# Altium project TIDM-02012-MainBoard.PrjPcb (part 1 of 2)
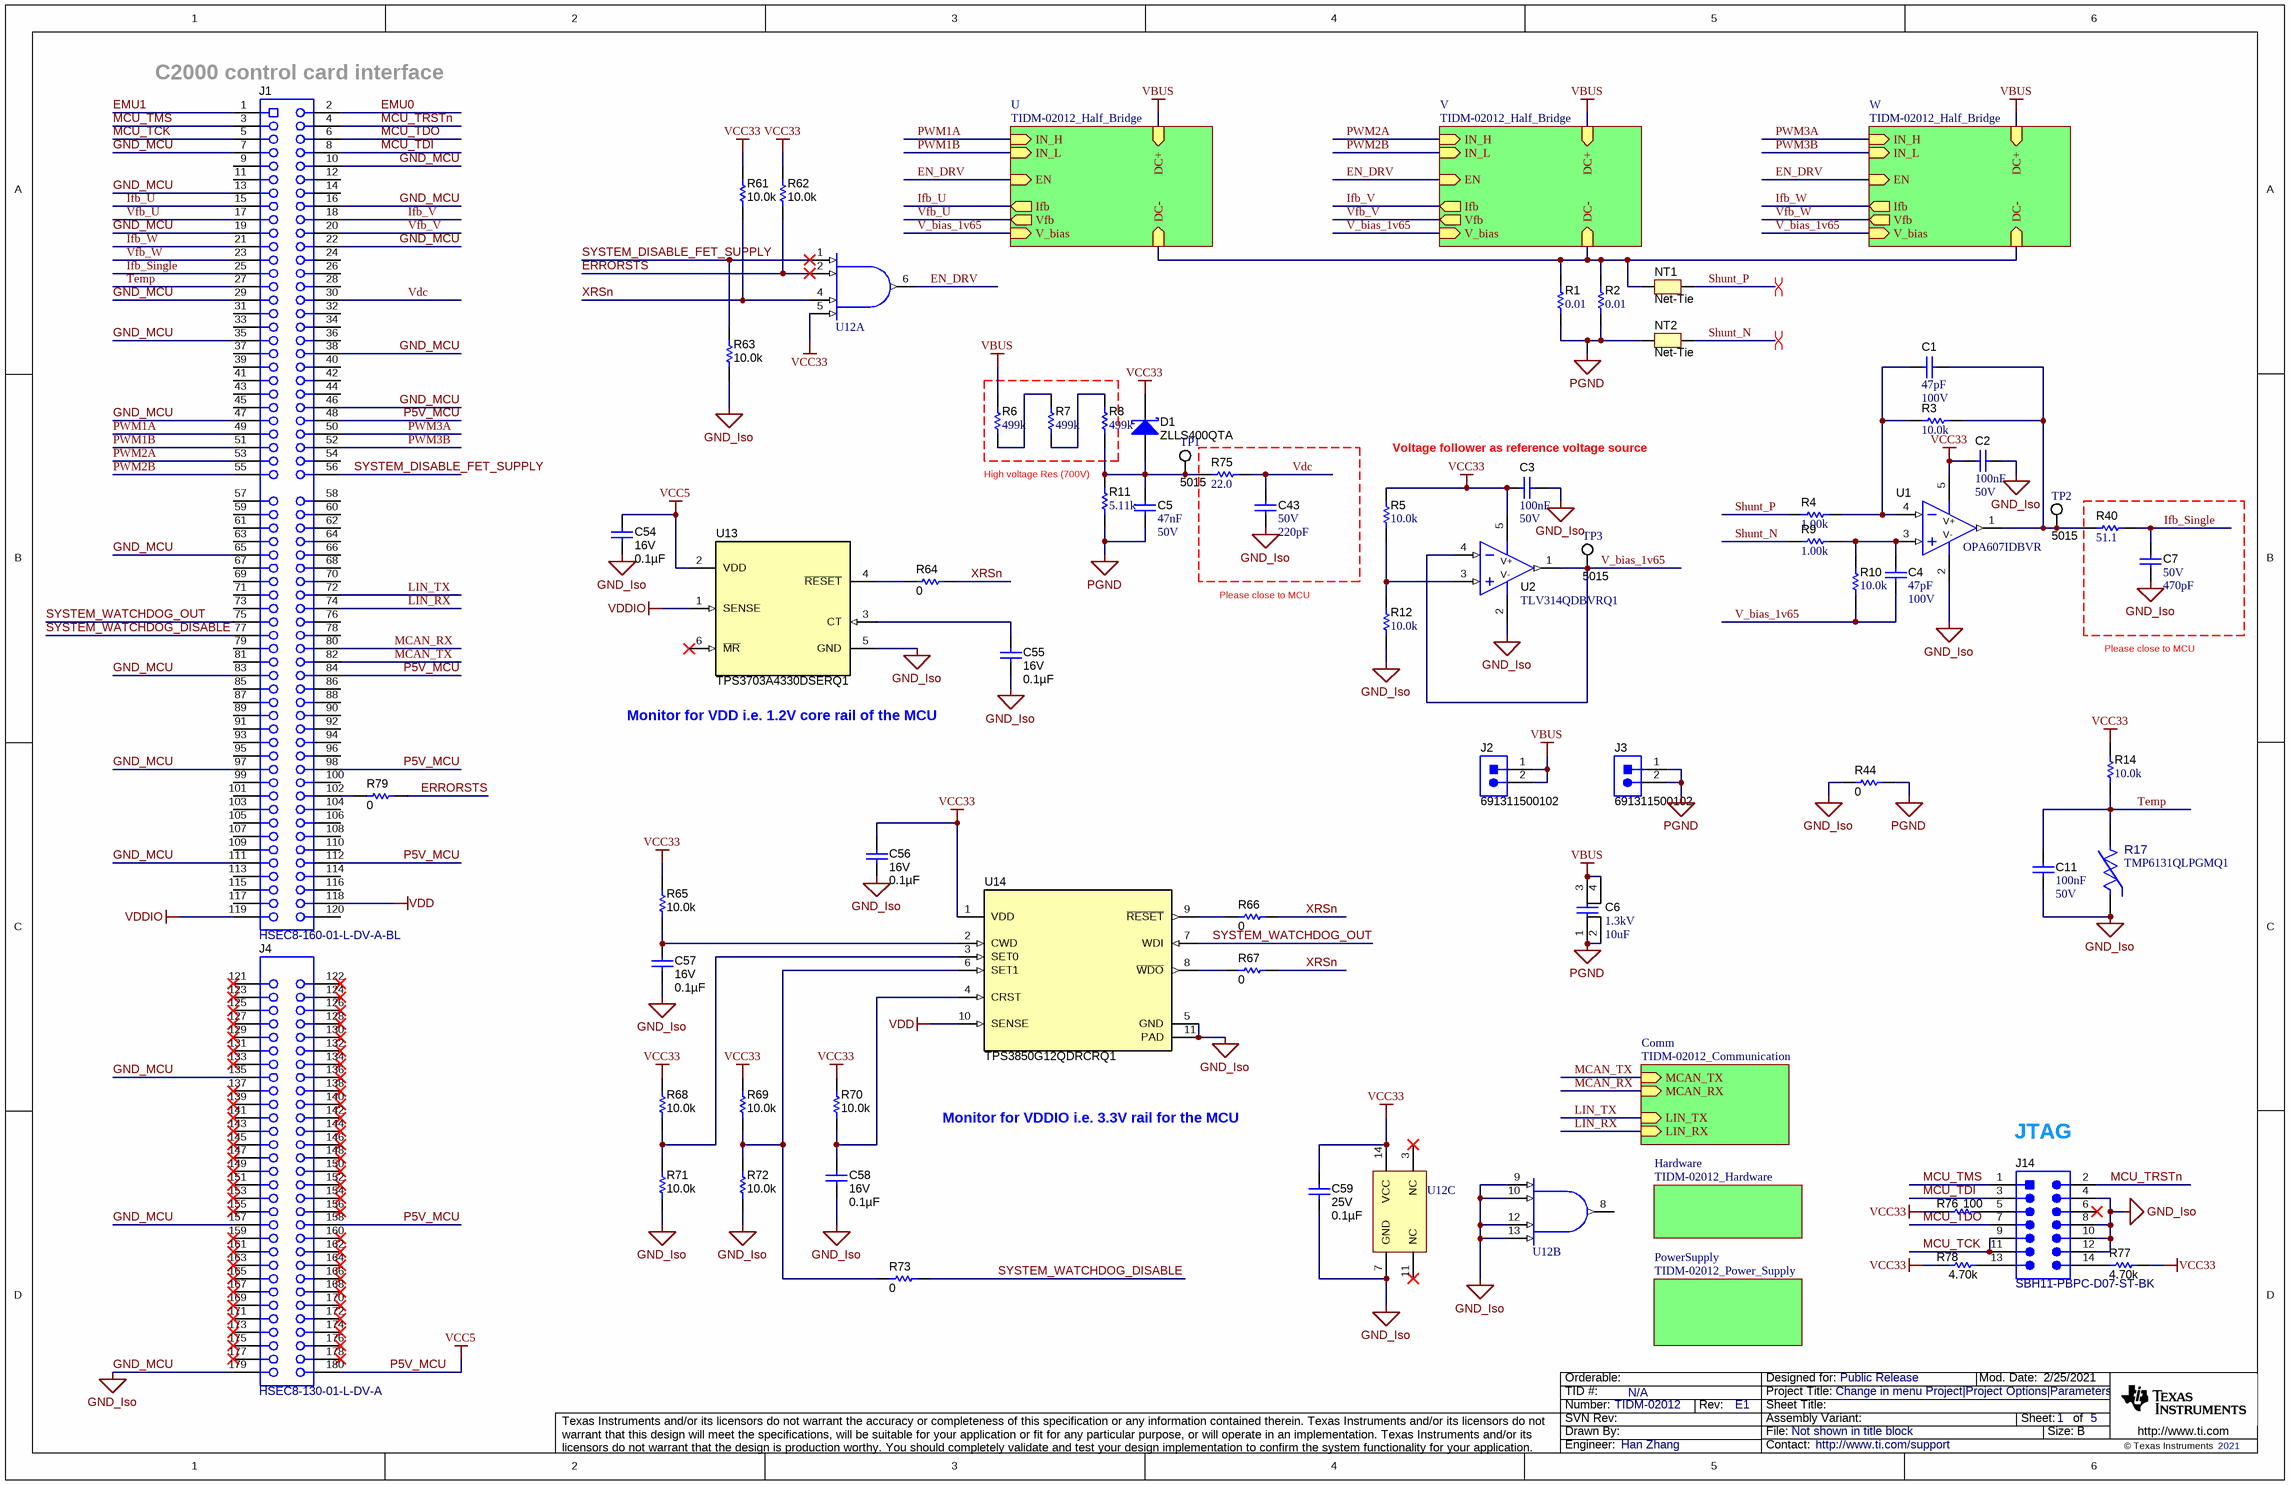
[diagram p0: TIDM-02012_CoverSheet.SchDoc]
CopyrightYear: 2021; PCB_Layout: Han Zhang; PCB_Rev: E1; PRJ_Customer: Public Release; PRJ_Engineer: Han Zhang; PRJ_Number: TIDM-02012; PRJ_Title: Change in menu Project|Project Options|Parameters; SCH_Rev: E1; TechSupport: http://www.ti.com/support; TID: N/A
5 sheets, 301 parts. Net scope: hierarchical (ports join the sheet entries above them; power ports are global).
Board file: TIDM-02012_MainBoard.PcbDoc
Sheets:
  TIDM-02012_CoverSheet.SchDoc
    PowerSupply = TIDM-02012_Power_Supply.SchDoc
    U = TIDM-02012_Half_Bridge.SchDoc
    Hardware = TIDM-02012_Hardware.SchDoc
    W = TIDM-02012_Half_Bridge.SchDoc
    V = TIDM-02012_Half_Bridge.SchDoc
    Comm = TIDM-02012_Communication.SchDoc

## Sheet TIDM-02012_CoverSheet.SchDoc
size 431 x 279 mm; Date: Not shown in title block; ApprovedBy: Not shown in title block; CheckedBy: Not shown in title block; Author: Not shown in title block; CompanyName: Not shown in title block; Engineer: Not shown in title block; Organization: Not shown in title block; Address1: Not shown in title block; Address2: Not shown in title block; Address3: Not shown in title block; Address4: Not shown in title block; DocumentNumber: 2; Revision: Use project parameter SCH_Rev; SheetNumber: 1; SheetTotal: 5; PageSetup: Record=PageOptions¦CenterHorizontal=True¦CenterVertical=True¦PrintScale=1.00¦XCorrection=1.00¦YCorrection=1.00¦PrintKind=0¦BorderSize=5000000¦LeftOffset=0¦BottomOffset=0¦Orientation=2¦PaperLength=1000¦PaperWidth=1000¦Scale=100¦PaperSource=15¦PrintQuality=600¦MediaType=1¦DitherType=10¦PaperKind=Letter¦PrintScaleMode=1

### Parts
C1  ValueDisplayed: 47pF  VDC_V: 100V  [0603]  (hidden comment: C0603C470J1GACAUTO)
C2  Cap_F: 100nF  VDC_V: 50V  [0603]  (hidden comment: C0603C104K5RACTU)
C3  Cap_F: 100nF  VDC_V: 50V  [0603]  (hidden comment: C0603C104K5RACTU)
C4  ValueDisplayed: 47pF  VDC_V: 100V  [0603]  (hidden comment: C0603C470J1GACAUTO)
C5  Cap_F: 47nF  VDC_V: 50V  [0603]  (hidden comment: 06035C473JAT2A)
C6  VDC_V: 1.3kV  ValueDisplayed: 10uF  [B32776_4200x2800x3700]  (hidden comment: B32776G1106K)
C7  VDC_V: 50V  ValueDisplayed: 470pF  [0603]  (hidden comment: GRM1885C1H471JA01D)
C11  Cap_F: 100nF  VDC_V: 50V  [0603]  (hidden comment: C0603C104K5RACTU)
C43  VDC_V: 50V  ValueDisplayed: 220pF  [0603]  (hidden comment: GRM1885C1H221JA01D)
C54  VDC_V: 16V  ValueDisplayed: 0.1µF  [0402]  (hidden comment: GCM155R71C104JA55D)
C55  VDC_V: 16V  ValueDisplayed: 0.1µF  [0402]  (hidden comment: GCM155R71C104JA55D)
C56  VDC_V: 16V  ValueDisplayed: 0.1µF  [0402]  (hidden comment: GCM155R71C104JA55D)
C57  VDC_V: 16V  ValueDisplayed: 0.1µF  [0402]  (hidden comment: GCM155R71C104JA55D)
C58  VDC_V: 16V  ValueDisplayed: 0.1µF  [0402]  (hidden comment: GCM155R71C104JA55D)
C59  VDC_V: 25V  ValueDisplayed: 0.1µF  [0402]  (hidden comment: CGA2B3X7R1E104K050BB)
D1  ZLLS400QTA  [SOD-323]
J1  HSEC8-160-01-L-DV-A-BL  [controlCARD-120HSEC]
J2  691311500102  [Wurth_691311500102]
J3  691311500102  [Wurth_691311500102]
J4  HSEC8-130-01-L-DV-A  [controlCARD-180HSEC-60pinAddon]
J14  SBH11-PBPC-D07-ST-BK  [CONN_SBH11-PBPC-D07-ST-BK]
NT1  Net-Tie  [Net-Tie_10milWide_30milLong]  (net tie, no BOM)
NT2  Net-Tie  [Net-Tie_10milWide_30milLong]  (net tie, no BOM)
R1  ValueDisplayed: 0.01  [1206]  (hidden comment: WSLP1206R0100FEA)
R2  ValueDisplayed: 0.01  [1206]  (hidden comment: WSLP1206R0100FEA)
R3  ValueDisplayed: 10.0k  [0603]  (hidden comment: RC0603FR-0710KL)
R4  ValueDisplayed: 1.00k  [0603]  (hidden comment: RC0603FR-071KL)
R5  ValueDisplayed: 10.0k  [0603]  (hidden comment: RC0603FR-0710KL)
R6  ValueDisplayed: 499k  [1206]  (hidden comment: ERJ-8ENF4993V)
R7  ValueDisplayed: 499k  [1206]  (hidden comment: ERJ-8ENF4993V)
R8  ValueDisplayed: 499k  [1206]  (hidden comment: ERJ-8ENF4993V)
R9  ValueDisplayed: 1.00k  [0603]  (hidden comment: RC0603FR-071KL)
R10  ValueDisplayed: 10.0k  [0603]  (hidden comment: RC0603FR-0710KL)
R11  ValueDisplayed: 5.11k  [1206]  (hidden comment: ERJ-8ENF5111V)
R12  ValueDisplayed: 10.0k  [0603]  (hidden comment: RC0603FR-0710KL)
R14  ValueDisplayed: 10.0k  [0603]  (hidden comment: RC0603FR-0710KL)
R17  TMP6131QLPGMQ1  [LPG0002A-MFG]
R40  ValueDisplayed: 51.1  [0603]  (hidden comment: RC0603FR-0751R1L)
R44  ValueDisplayed: 0  [0402]  (hidden comment: ERJ-2GE0R00X)
R61  ValueDisplayed: 10.0k  [0402]  (hidden comment: ERJPA2F1002X)
R62  ValueDisplayed: 10.0k  [0402]  (hidden comment: ERJPA2F1002X)
R63  ValueDisplayed: 10.0k  [0402]  (hidden comment: ERJPA2F1002X)
R64  ValueDisplayed: 0  [0402]  (hidden comment: ERJ-2GE0R00X)
R65  ValueDisplayed: 10.0k  [0402]  (hidden comment: ERJPA2F1002X)
R66  ValueDisplayed: 0  [0402]  (hidden comment: ERJ-2GE0R00X)
R67  ValueDisplayed: 0  [0402]  (hidden comment: ERJ-2GE0R00X)
R68  ValueDisplayed: 10.0k  [0402]  (hidden comment: ERJPA2F1002X)
R69  ValueDisplayed: 10.0k  [0402]  (hidden comment: ERJPA2F1002X)
R70  ValueDisplayed: 10.0k  [0402]  (hidden comment: ERJPA2F1002X)
R71  ValueDisplayed: 10.0k  [0402]  (hidden comment: ERJPA2F1002X)
R72  ValueDisplayed: 10.0k  [0402]  (hidden comment: ERJPA2F1002X)
R73  ValueDisplayed: 0  [0402]  (hidden comment: ERJ-2GE0R00X)
R75  ValueDisplayed: 22.0  [0603]  (hidden comment: RC0603FR-0722RL)
R76  ValueDisplayed: 100  [0603]  (hidden comment: ERJ-3EKF1000V)
R77  ValueDisplayed: 4.70k  [0603]  (hidden comment: RC0603FR-074K7L)
R78  ValueDisplayed: 4.70k  [0603]  (hidden comment: RC0603FR-074K7L)
R79  ValueDisplayed: 0  [0402]  (hidden comment: ERJ-2GE0R00X)
TP1  5015  [Testpoint_Keystone_Miniature]
TP2  5015  [Testpoint_Keystone_Miniature]
TP3  5015  [Testpoint_Keystone_Miniature]
U1  OPA607IDBVR  [DBV0005A_N]
U2  TLV314QDBVRQ1  [DBV0005A_N]
U12  SN74HC21QPWRG4Q1  [PW0014A_N]  (value not drawn)  (parts A,B,C of 3)
U13  TPS3703A4330DSERQ1  [DSE0006A]
U14  TPS3850G12QDRCRQ1  [DRC0010R]

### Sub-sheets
Comm = TIDM-02012_Communication: LIN_RX (in), MCAN_TX (in), MCAN_RX (in), LIN_TX (in)
Hardware = TIDM-02012_Hardware: no entries
PowerSupply = TIDM-02012_Power_Supply: no entries
U = TIDM-02012_Half_Bridge: DC+ (in), IN_H (in), IN_L (in), DC- (in), V_bias (in), Ifb (out), EN (in), Vfb (out)
V = TIDM-02012_Half_Bridge: DC+ (in), IN_H (in), IN_L (in), DC- (in), V_bias (in), Ifb (out), EN (in), Vfb (out)
W = TIDM-02012_Half_Bridge: DC+ (in), IN_H (in), IN_L (in), DC- (in), V_bias (in), Ifb (out), EN (in), Vfb (out)

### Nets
GND_MCU: C2.1 C3.1 C7.2 C11.1 C43.2 C54.2 C55.2 C56.2 C57.2 C58.2 C59.2 J1.7 J1.10 J1.13 J1.16 J1.19 J1.22 J1.29 J1.35 J1.38 J1.46 J1.47 J1.65 J1.83 J1.97 J1.111 J4.135 J4.157 J4.179 J14.4 J14.8 J14.10 J14.12 R12.1 R17.1(-) R44.1 R63.1 R71.1 R72.1 U1.2(V-) U2.2(V-) U12.7(GND) U12.9(2A) U12.10(2B) U12.12(2C) U12.13(2D) U13.5(GND) U14.5(GND) U14.11(PAD)  [also labelled GND_Iso]
P5V_MCU: C54.1 J1.48 J1.84 J1.98 J1.112 J4.158 J4.180 U13.2(VDD)  [also labelled VCC5]
PGND: C5.2 C6.1 C6.2 J3.1 J3.2 NT2.1 R1.1 R2.1 R11.1 R44.2
VBUS: C6.3 C6.4 J2.1 J2.2 R6.2 ; sheet U/DC+, sheet W/DC+, sheet V/DC+
VCC33: C2.2 C3.2 C56.1 C59.1 D1.1(K) R5.2 R14.2 R61.2 R62.2 R65.2 R68.2 R69.2 R70.2 R76.1 R77.2 R78.1 U1.5(V+) U2.5(V+) U12.5(1D) U12.14(VCC) U14.1(VDD)
VDD: J1.118 U14.10(SENSE)
VDDIO: J1.119 U13.1(SENSE)
DC-: NT1.1 R1.2 R2.2 ; sheet U/DC-, sheet W/DC-, sheet V/DC-
EMU0: J1.2
EMU1: J1.1
EN_DRV: U12.6(1Y) ; sheet U/EN, sheet W/EN, sheet V/EN
ERRORSTS: R62.1 R79.2 U12.2(1B)
Ifb_Single: C7.1 J1.25 R40.2
Ifb_U: J1.15 ; sheet U/Ifb
Ifb_V: J1.18 ; sheet V/Ifb
Ifb_W: J1.21 ; sheet W/Ifb
LIN_RX: J1.74 ; sheet Comm/LIN_RX
LIN_TX: J1.72 ; sheet Comm/LIN_TX
MCAN_RX: J1.80 ; sheet Comm/MCAN_RX
MCAN_TX: J1.82 ; sheet Comm/MCAN_TX
MCU_TCK: J1.5 J14.9 J14.11
MCU_TDI: J1.8 J14.3
MCU_TDO: J1.6 J14.7
MCU_TMS: J1.3 J14.1
MCU_TRSTn: J1.4 J14.2
PWM1A: J1.49 ; sheet U/IN_H
PWM1B: J1.51 ; sheet U/IN_L
PWM2A: J1.53 ; sheet V/IN_H
PWM2B: J1.55 ; sheet V/IN_L
PWM3A: J1.50 ; sheet W/IN_H
PWM3B: J1.52 ; sheet W/IN_L
Shunt_N: NT2.2 R9.1
Shunt_P: NT1.2 R4.1
SYSTEM_DISABLE_FET_SUPPLY: J1.56 R63.2 U12.1(1A)
SYSTEM_WATCHDOG_DISABLE: J1.77 R73.2
SYSTEM_WATCHDOG_OUT: J1.75 U14.7(WDI)
Temp: C11.2 J1.27 R14.1 R17.2(+)
V_bias_1v65: C4.2 R10.1 TP3.1 U2.1(OUT) U2.4(IN-) ; sheet U/V_bias, sheet W/V_bias, sheet V/V_bias
Vdc: C43.1 J1.30 R75.2
Vfb_U: J1.17 ; sheet U/Vfb
Vfb_V: J1.20 ; sheet V/Vfb
Vfb_W: J1.23 ; sheet W/Vfb
XRSn: R61.1 R64.2 R66.2 R67.2 U12.4(1C)
NetC1_1: C1.1 R3.2 R40.1 TP2.1 U1.1(OUT)
NetC1_2: C1.2 R3.1 R4.2 U1.4(IN-)
NetC4_1: C4.1 R9.2 R10.2 U1.3(IN+)
NetC5_1: C5.1 D1.2(A) R8.1 R11.2 R75.1 TP1.1
NetC55_1: C55.1 U13.3(CT)
NetC57_1: C57.1 R65.1 U14.2(CWD)
NetC58_1: C58.1 R70.1 U14.4(CRST)
NetJ1_102: J1.102 R79.1
NetJ14_5: J14.5 R76.2
NetJ14_13: J14.13 R78.2
NetJ14_14: J14.14 R77.1
NetR5_1: R5.1 R12.2 U2.3(IN+)
NetR6_1: R6.1 R7.2
NetR7_1: R7.1 R8.2
NetR64_1: R64.1 U13.4(~{RESET})
NetR66_1: R66.1 U14.9(~{RESET})
NetR67_1: R67.1 U14.8(~{WDO})
NetR68_1: R68.1 R71.2 U14.3(SET0)
NetR69_1: R69.1 R72.2 R73.1 U14.6(SET1)

Not connected (* = marked no-connect by the designer): J1 9 11 12 14 24 26 28 31 32 33 34 36 37 39 40 41 42 43 44 45 54 57 58 59 60 61 62 63 64 66 67 68 69 70 71 73 76 78 79 81 85 86 87 88 89 90 91 92 93 94 95 96 99 100 101 103 104 105 106 107 108 109 110 113 114 115 116 117 120; J4 121* 122* 123* 124* 125* 126* 127* 128* 129* 130* 131* 132* 133* 134* 136* 137* 138* 139* 140* 141* 142* 143* 144* 145* 146* 147* 148* 149* 150* 151* 152* 153* 154* 155* 156* 159* 160* 161* 162* 163* 164* 165* 166* 167* 168* 169* 170* 171* 172* 173* 174* 175* 176* 177* 178*; J14 6*; U12 3(NC)* 8(2Y) 11(NC)*; U13 6(~{MR})*

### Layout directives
differential pair: Shunt_N, Shunt_P

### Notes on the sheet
- (near J1) C2000 control card interface
- (near R11) High voltage Res (700V)
- Voltage follower as reference voltage source
- Please close to MCU
- Monitor for VDD i.e. 1.2V core rail of the MCU
- Monitor for VDDIO i.e. 3.3V rail for the MCU
- (near J14) JTAG

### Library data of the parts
C1 C4 = CMP-0085572-1: CAP, CERM, 47 pF, 100 V,+/- 5%, C0G/NP0, AEC-Q200 Grade 1, 0603; Manufacturer: Kemet; TaMax_C: 125°C; AEC Category: Q200; AEC Grade: 1; TaMin_C: -55°C; SizeArea_mm2: 1.28; Value: 47pF; AEC Qualified: Y; Polarized: N; SizeX_mm: 1.6; U/M: EA; SizeY_mm: 0.8; SizeAreaWB_mm2: 4.68
C2 C3 C11 = CMP-0006861-4: CAP, CERM, 0.1 uF, 50 V, +/- 10%, X7R, 0603; Manufacturer: Kemet; TaMin_C: -55°C; Polarized: N; SizeAreaWB_mm2: 4.68; Value1: Unknown; U/M: EA; Value: 0.1uF; TaMax_C: 125°C; SizeZ_mm: 1; SizeX_mm: 1.6; SizeY_mm: 0.8; SizeArea_mm2: 1.28; AEC Category: Q200
C5 = CMP-0085252-1: CAP, CERM, 0.047 µF, 50 V,+/- 5%, X7R, 0603; Manufacturer: AVX; TaMax_C: 125°C; Value: 0.047uF; SizeX_mm: 1.6; SizeArea_mm2: 1.28; AEC Category: Q200; SizeY_mm: 0.8; Polarized: N; SizeAreaWB_mm2: 4.68; U/M: EA; TaMin_C: -55°C; SizeZ_mm: 1
C6 = CMP-0012359-3: CAP, Film, 10 uF, 1300 V, +/- 10%, 0.0065 ohm, AEC-Q200 Grade 2, TH; Manufacturer: TDK; TaMin_C: -40°C; ESR_ohm: 6.5m; Polarized: N; SizeAreaWB_mm2: 1320; Value: 10uF; TaMax_C: 105°C; SizeZ_mm: 37; SizeX_mm: 42; SizeY_mm: 28; Cap_Case: 42x28x37mm; Value2: 1300V; SizeArea_mm2: 1176; CompType: Capacitor; AEC Qualified: Y; Cap_F: 10µF; AEC Grade: 2; AEC Category: Q200
C7 = CMP-0007221-4: CAP, CERM, 470 pF, 50 V, +/- 5%, C0G/NP0, 0603; Manufacturer: MuRata; TaMin_C: -55°C; Polarized: N; SizeAreaWB_mm2: 4.68; Value1: Unknown; U/M: EA; Value: 470pF; TaMax_C: 125°C; SizeZ_mm: 1; SizeX_mm: 1.6; SizeY_mm: 0.8; SizeArea_mm2: 1.28; AEC Category: Q200
C43 = CMP-0007197-4: CAP, CERM, 220 pF, 50 V, +/- 5%, C0G/NP0, 0603; Manufacturer: MuRata; TaMin_C: -55°C; Polarized: N; SizeAreaWB_mm2: 4.68; Value1: Unknown; U/M: EA; Value: 220pF; TaMax_C: 125°C; SizeZ_mm: 1; SizeX_mm: 1.6; SizeY_mm: 0.8; SizeArea_mm2: 1.28; AEC Category: Q200
C54-C58 = CMP-0080702-1: CAP, CERM, 0.1 µF, 16 V,+/- 5%, X7R, AEC-Q200 Grade 1, 0402; Manufacturer: MuRata; Cap_F: 100nF; SizeAreaWB_mm2: 3; SizeArea_mm2: 0.5; AEC Qualified: Y; AEC Category: Q200; Value: 0.1uF; TaMax_C: 125°C; SizeZ_mm: 0.6; AEC Grade: 1; Polarized: N; TaMin_C: -55°C; U/M: EA
C59 = CMP-0080610-1: CAP, CERM, 0.1 µF, 25 V,+/- 10%, X7R, AEC-Q200 Grade 1, 0402; Manufacturer: TDK; TaMin_C: -55°C; Polarized: N; SizeAreaWB_mm2: 3; U/M: EA; Value: 0.1uF; TaMax_C: 125°C; SizeZ_mm: 0.6; SizeX_mm: 1; SizeY_mm: 0.5; AEC Qualified: Y; Cap_F: 100nF; AEC Category: Q200
D1 = CMP-0028792-2: Diode, Schottky, 40 V, 0.52 A, AEC-Q101, SOD-323; Manufacturer: Diodes Inc.; Value: 40V; SizeZ_mm: 1; Io_A: 520mA; SizeAreaWB_mm2: 8.695; SizeArea_mm2: 3.645; TJmax_C: 150°C; Green_REACh: Incomplete; SizeX_mm: 2.7; AEC Category: Q101; Value1: 0.52A; SizeY_mm: 1.35; AEC Qualified: Y; Green_Lifecycle: Not Set
J1 = CMP-0003814-2: C2000 controlCARD-120HSEC connector, SMT; Manufacturer: Samtec; Note: The pin numbering does not match Samtec datasheet
J2 J3 = CMP-0084907-1: Terminal Block, 2 Pos, 5.08mm, Tin, TH; Manufacturer: Wurth Elektronik; Row_Count: 1; Voltage_V: 300V; Shrouded: Y; Gender: Male; Current_A: 20A; Pitch_mm: 5.08
J4 = CMP-0003859-2: C2000 controlCARD-180HSEC (60-pin addon) connector, SMT; Manufacturer: Samtec; Note: The pin numbering does not match Samtec datasheet
J14 = CMP-0054695-2: Header (shrouded), 100 mil, 7x2, Gold, TH; Manufacturer: Sullins Connector Solutions; Green_REACh: Incomplete; Green_Lifecycle: Not Set
NT1 NT2 = CMP-0078142-4: Single point connection between nets.
R1 R2 = CMP-0018570-2: RES, 0.01, 1%, 1 W, 1206; Manufacturer: Vishay-Dale; Power_W: 1W; TempCo: 75 ppm/C; Value_Code: R010; U/M: EA; Value: 0.01; EIA_Code: E96; Res_ohm: 10m; SizeX_mm: 3.2; SizeY_mm: 1.6; SizeZ_mm: 1.35; SizeArea_mm2: 5.12; AEC Category: Q200
R3 R5 R10 R12 R14 = CMP-0022746-5: RES, 10.0 k, 1%, 0.1 W, 0603; Manufacturer: Yageo; Power_W: 100mW; TempCo: 100 ppm/C; Value_Code: 10k0; Value: 10.0k; EIA_Code: E96; Res_ohm: 10k; SizeX_mm: 1.6; SizeY_mm: 0.8; SizeZ_mm: 1; Value2: 0.1W; SizeArea_mm2: 1.28; AEC Qualified: N; VDC_V: 75V; AEC Category: Q200; SizeAreaWB_mm2: 4.68
R4 R9 = CMP-0022895-5: RES, 1.00 k, 1%, 0.1 W, 0603; Manufacturer: Yageo; Power_W: 100mW; TempCo: 100 ppm/C; Value_Code: 1k00; Value: 1.00k; EIA_Code: E96; Res_ohm: 1k; SizeX_mm: 1.6; SizeY_mm: 0.8; SizeZ_mm: 1; Value2: 0.1W; SizeArea_mm2: 1.28; AEC Qualified: N; VDC_V: 75V; AEC Category: Q200; SizeAreaWB_mm2: 4.68
R6-R8 = CMP-0017631-3: RES, 499 k, 1%, 0.25 W, AEC-Q200 Grade 0, 1206; Manufacturer: Panasonic; Power_W: 250mW; TempCo: 100 ppm/C; Value: 499k; EIA_Code: E96; SizeX_mm: 3.2; SizeY_mm: 1.6; SizeZ_mm: 1.35; Value2: 0.25W; SizeArea_mm2: 5.12; AEC Qualified: Y; VDC_V: 200V; AEC Category: Q200; AEC Grade: 0; SizeAreaWB_mm2: 10.92
R11 = CMP-0017634-3: RES, 5.11 k, 1%, 0.25 W, AEC-Q200 Grade 0, 1206; Manufacturer: Panasonic; Power_W: 250mW; TempCo: 100 ppm/C; Value_Code: 5k11; Value: 5.11k; EIA_Code: E96; SizeX_mm: 3.2; SizeY_mm: 1.6; SizeZ_mm: 1.35; Value2: 0.25W; SizeArea_mm2: 5.12; AEC Qualified: Y; VDC_V: 200V; AEC Category: Q200; AEC Grade: 0; SizeAreaWB_mm2: 10.92
R17 = CMP-0088739-1: PTC Thermistor 10 kOhms TO-226-2, TO-92-2 (TO-226AC) Short Body; Manufacturer: Texas Instruments; VDC_V: 5.5V; Tolerance_%: 1%; Value: 10k; TempCo: 6400ppm/°C; TJmax_C: +150°C; AEC Qualified: Yes; AEC Grade: Grade 1; TaMax_C: +125°C; TaMin_C: -40°C; SizeZ_mm: 5.05mm
R40 = CMP-0023168-5: RES, 51.1, 1%, 0.1 W, 0603; Manufacturer: Yageo; Power_W: 100mW; TempCo: 100 ppm/C; Value_Code: 51R1; Value: 51.1; EIA_Code: E96; SizeX_mm: 1.6; SizeY_mm: 0.8; SizeZ_mm: 1; Value2: 0.1W; SizeArea_mm2: 1.28; AEC Qualified: N; VDC_V: 75V; AEC Category: Q200; SizeAreaWB_mm2: 4.68
R44 R64 R66 R67 R73 R79 = CMP-0026992-3: RES, 0, 5%, 0.1 W, AEC-Q200 Grade 0, 0402; Manufacturer: Panasonic; Power_W: 100mW; TempCo: 600 ppm/C; Value_Code: 0000; Value: 0; EIA_Code: E24; SizeX_mm: 1; SizeY_mm: 0.5; SizeZ_mm: 0.6; Value2: 0.1W; AEC Qualified: Y; VDC_V: 50V; AEC Category: Q200; SizeAreaWB_mm2: 3
R61-R63 R65 R68-R72 = CMP-0078779-1: RES, 10.0 k, 1%, 0.2 W, AEC-Q200 Grade 0, 0402; Manufacturer: Panasonic; Value_Code: 10k0; SizeArea_mm2: 0.5; AEC Qualified: Y; AEC Category: Q200; Res_ohm: 10k; Value: 10.0k; SizeZ_mm: 0.6; EIA_Code: E96; TempCo: 100 ppm/C; AEC Grade: 0; Power_W: 200mW; VDC_V: 50V; Value2: 0.2W; SizeX_mm: 1
R75 = CMP-0022928-4: RES, 22.0, 1%, 0.1 W, 0603; Manufacturer: Yageo; Power_W: 100mW; TempCo: 100 ppm/C; Value_Code: 22R0; Value: 22.0; Res_ohm: 22; SizeX_mm: 1.6; SizeY_mm: 0.8; SizeZ_mm: 1; Value2: 0.1W; SizeArea_mm2: 1.28; AEC Qualified: N; VDC_V: 75V; AEC Category: Q200; SizeAreaWB_mm2: 4.68
R76 = CMP-0022679-3: RES, 100, 1%, 0.1 W, AEC-Q200 Grade 0, 0603; Manufacturer: Panasonic; Power_W: 100mW; TempCo: 100 ppm/C; Value_Code: 100R; U/M: EA; Value: 100; EIA_Code: E96; SizeX_mm: 1.6; SizeY_mm: 0.8; SizeZ_mm: 1; Value2: 0.1W; SizeArea_mm2: 1.28; AEC Qualified: Y; AEC Grade: 0; AEC Category: Q200
R77 R78 = CMP-0023153-5: RES, 4.70 k, 1%, 0.1 W, 0603; Manufacturer: Yageo; Power_W: 100mW; TempCo: 100 ppm/C; Value_Code: 4k70; Value: 4.70k; Res_ohm: 4.7k; SizeX_mm: 1.6; SizeY_mm: 0.8; SizeZ_mm: 1; Value2: 0.1W; SizeArea_mm2: 1.28; AEC Qualified: N; VDC_V: 75V; AEC Category: Q200; SizeAreaWB_mm2: 4.68
TP1-TP3 = CMP-0055152-1: Test Point, Miniature, SMT; Manufacturer: Keystone; CNHeader: FALSE; Green_Lifecycle: Active; Green_REACh: Passed; CT: TRUE
U1 = CMP-0861047-2: 50-MHz, Low-Power, Gain of 6-V/V Stable, Rail-to-Rail Output CMOS Operational Amplifier, DBV0005A (SOT-23-5); Manufacturer: Texas Instruments; AEC Category: Q200; SizeY_mm: 2.9; SizeArea_mm2: 8.12; SizeX_mm: 2.8; SizeZ_mm: 1.45; SizeAreaWB_mm2: 14.82; AEC Qualified: N; CompType: IC
U2 = CMP-0073534-1: 3-MHz, Low-Power, Internal EMI Filter, RRIO, Operational Amplifier, DBV0005A (SOT-23-5); Alternate PartNumber: TLV314QDBVTQ1; Alternate Manufacturer: Texas Instruments; SizeAreaWB_mm2: 14.82; U/M: EA; SizeZ_mm: 1.45; SizeX_mm: 2.8; SizeY_mm: 2.9; SizeArea_mm2: 8.12; CompType: IC
U12 = CMP-0054468-2: Automotive Catalog Dual 4-Input Positive-AND Gates, PW0014A, LARGE T&R; Generic Part Number: SN74HC21-Q1; Manufacturer: Texas Instruments; Output Type: CMOS; VCC(Min)(V): 2; Voltage(Nom)(V): 5; F @ Nom Voltage(Max)(Mhz): 70; tpd @ Nom Voltage(Max)(ns): 140; Output Drive (IOL/IOH)(Max)(mA): -5.2/5.2; VCC(Max)(V): 6; Schmitt Trigger: No; Technology Family: HC; ICC @ Nom Voltage(Max)(mA): 0.02; AEC Category: Q200; CompType: IC
U13 = CMP-0750051-1: Overvoltage and Undervoltage Reset IC With Time Delay and Manual Reset, DSE0006A (WSON-6); Alternate Manufacturer: Texas Instruments; AEC Category: Q200; SizeY_mm: 1.5; AEC Qualified: Y; SizeAreaWB_mm2: 6.25; SizeZ_mm: 0.8; SizeArea_mm2: 2.25
U14 = CMP-0081428-2: Automotive Precision Voltage Supervisor With Programmable Window Watchdog Timer, DRC0010R (VSON-10); Alternate Manufacturer: Texas Instruments; SizeAreaWB_mm2: 16; SizeZ_mm: 1; SizeX_mm: 3; SizeArea_mm2: 9; CompType: IC; AEC Qualified: Y; AEC Category: Q200

## Sheet TIDM-02012_Power_Supply.SchDoc
size 431 x 279 mm; Date: Not shown in title block; ApprovedBy: Not shown in title block; CheckedBy: Not shown in title block; Author: Not shown in title block; CompanyName: Not shown in title block; Engineer: Not shown in title block; Organization: Not shown in title block; Address1: Not shown in title block; Address2: Not shown in title block; Address3: Not shown in title block; Address4: Not shown in title block; DocumentNumber: 2; Revision: Use project parameter SCH_Rev; SheetNumber: 4; SheetTotal: 5; PageSetup: Record=PageOptions¦CenterHorizontal=True¦CenterVertical=True¦PrintScale=1.00¦XCorrection=1.00¦YCorrection=1.00¦PrintKind=0¦BorderSize=5000000¦LeftOffset=0¦BottomOffset=0¦Orientation=2¦PaperLength=1000¦PaperWidth=1000¦Scale=100¦PaperSource=15¦PrintQuality=600¦MediaType=1¦DitherType=10¦PaperKind=Letter¦PrintScaleMode=1
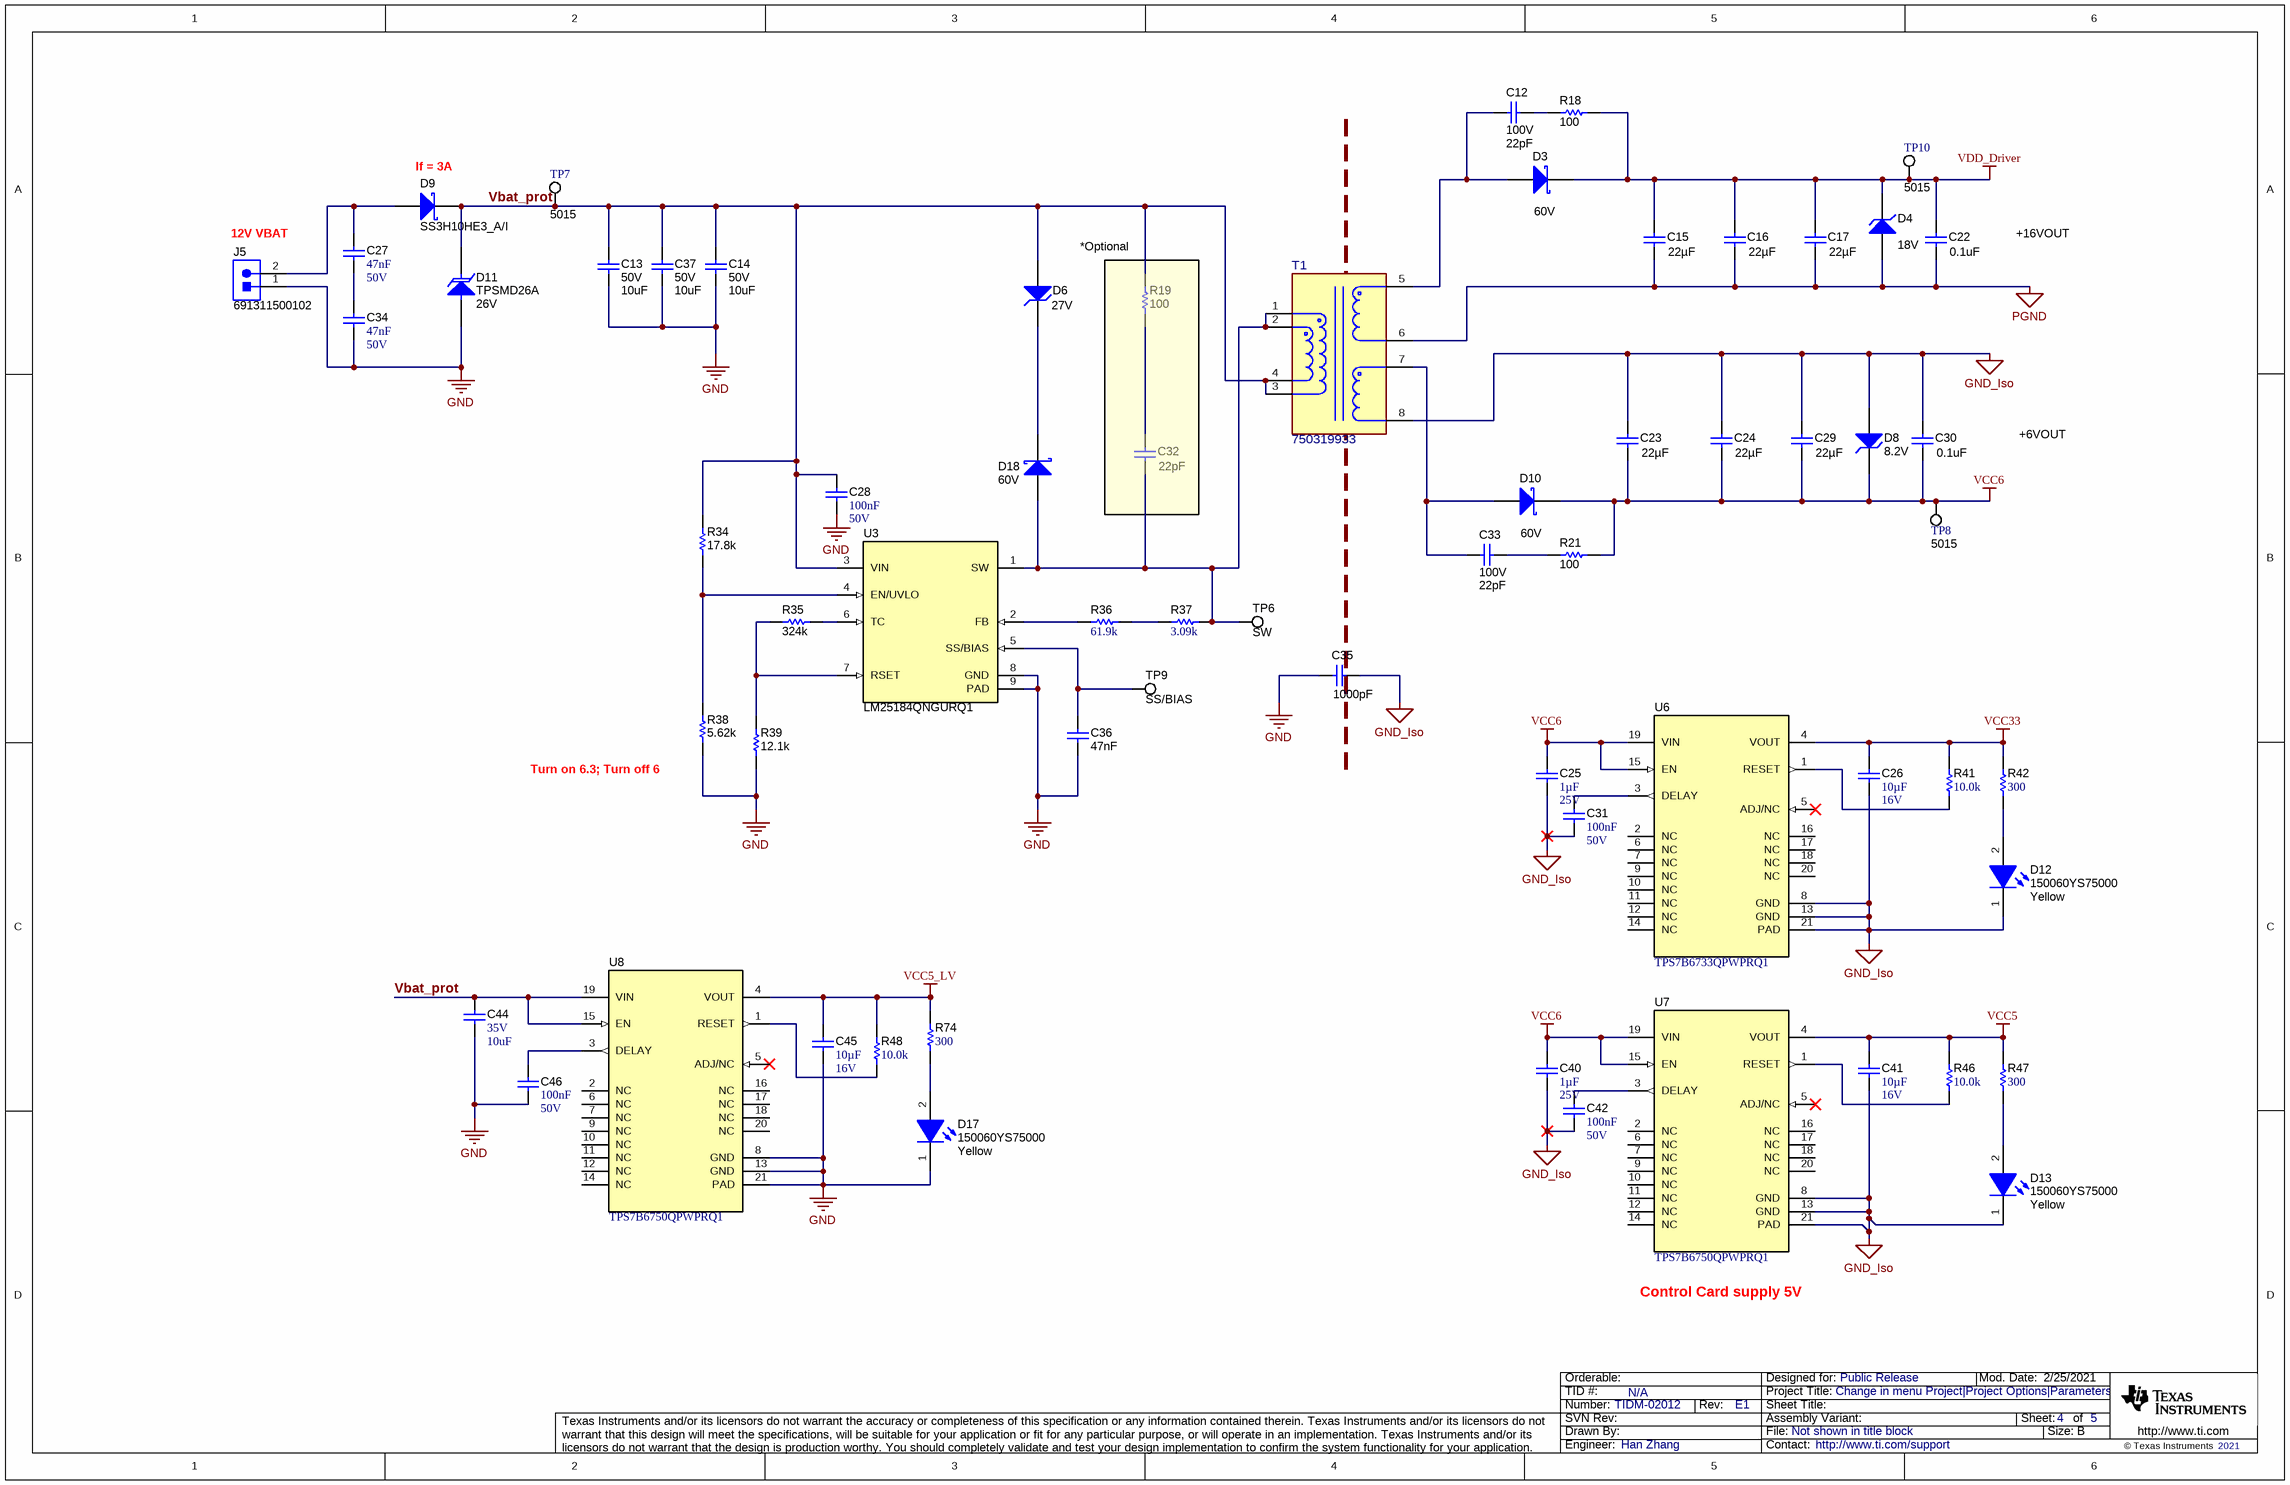
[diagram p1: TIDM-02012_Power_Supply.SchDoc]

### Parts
C12  VDC_V: 100V  ValueDisplayed: 22pF  [0603]  (hidden comment: GRM1885C2A220JA01D)
C13  VDC_V: 50V  ValueDisplayed: 10uF  [1210_280]  (hidden comment: CGA6P3X7S1H106K250AB)
C14  VDC_V: 50V  ValueDisplayed: 10uF  [1210_280]  (hidden comment: CGA6P3X7S1H106K250AB)
C15  ValueDisplayed: 22µF  [1210_270]  (hidden comment: TMK325B7226KMHP)
C16  ValueDisplayed: 22µF  [1210_270]  (hidden comment: TMK325B7226KMHP)
C17  ValueDisplayed: 22µF  [1210_270]  (hidden comment: TMK325B7226KMHP)
C22  value 0.1uF  [0603]  (hidden comment: C0603C104K5RACAUTO)
C23  ValueDisplayed: 22µF  [1210_270]  (hidden comment: TMK325B7226KMHP)
C24  ValueDisplayed: 22µF  [1210_270]  (hidden comment: TMK325B7226KMHP)
C25  Cap_F: 1µF  VDC_V: 25V  [0603]  (hidden comment: CGA3E1X7R1E105M080AC)
C26  Cap_F: 10µF  VDC_V: 16V  [0805_HV]  (hidden comment: EMK212BB7106MG-T)
C27  Cap_F: 47nF  VDC_V: 50V  [0603]  (hidden comment: CGA3E2X7R1H473K080AA)
C28  Cap_F: 100nF  VDC_V: 50V  [0603]  (hidden comment: C0603C104K5RACTU)
C29  ValueDisplayed: 22µF  [1210_270]  (hidden comment: TMK325B7226KMHP)
C30  value 0.1uF  [0603]  (hidden comment: C0603C104K5RACAUTO)
C31  Cap_F: 100nF  VDC_V: 50V  [0603]  (hidden comment: C0603C104K5RACTU)
C32  ValueDisplayed: 22pF  [0603_HV]  (hidden comment: GRM1885C2A220JA01D)
C33  VDC_V: 100V  ValueDisplayed: 22pF  [0603]  (hidden comment: GRM1885C2A220JA01D)
C34  Cap_F: 47nF  VDC_V: 50V  [0603]  (hidden comment: CGA3E2X7R1H473K080AA)
C35  ValueDisplayed: 1000pF  [1206_190M]  (hidden comment: 202R18W102KV4E)
C36  Cap_F: 47nF  [0603]  (hidden comment: GCM188R71E473KA37D)
C37  VDC_V: 50V  ValueDisplayed: 10uF  [1210_280]  (hidden comment: CGA6P3X7S1H106K250AB)
C40  Cap_F: 1µF  VDC_V: 25V  [0603]  (hidden comment: CGA3E1X7R1E105M080AC)
C41  Cap_F: 10µF  VDC_V: 16V  [0805_HV]  (hidden comment: EMK212BB7106MG-T)
C42  Cap_F: 100nF  VDC_V: 50V  [0603]  (hidden comment: C0603C104K5RACTU)
C44  VDC_V: 35V  ValueDisplayed: 10uF  [1206]  (hidden comment: GMK316AB7106KL)
C45  Cap_F: 10µF  VDC_V: 16V  [0805_HV]  (hidden comment: EMK212BB7106MG-T)
C46  Cap_F: 100nF  VDC_V: 50V  [0603]  (hidden comment: C0603C104K5RACTU)
D3  value 60V  [SOD-123HE]  (hidden comment: FSV360FP)
D4  value 18V  [SOD-523]  (hidden comment: BZT52C18T-7)
D6  value 27V  [SMA]  (hidden comment: 3SMAJ5935B-TP)
D8  value 8.2V  [SOD-523]  (hidden comment: BZT52C8V2T-7)
D9  SS3H10HE3_A/I  [SMC_265]
D10  value 60V  [SOD-123HE]  (hidden comment: FSV360FP)
D11  TPSMD26A  value 26V  [SMC_265]
D12  150060YS75000  value Yellow  [WL-SMCW_YELLOW]
D13  150060YS75000  value Yellow  [WL-SMCW_YELLOW]
D17  150060YS75000  value Yellow  [WL-SMCW_YELLOW]
D18  value 60V  [SOD-123W]  (hidden comment: PMEG60T30ELRX)
J5  691311500102  [Wurth_691311500102]
R18  ValueDisplayed: 100  [0603]  (hidden comment: CRCW0603100RFKEAHP)
R19  ValueDisplayed: 100  [0603]  (hidden comment: CRCW0603100RFKEA)
R21  ValueDisplayed: 100  [0603]  (hidden comment: CRCW0603100RFKEAHP)
R34  ValueDisplayed: 17.8k  [0603]  (hidden comment: RC0603FR-0717K8L)
R35  ValueDisplayed: 324k  [0603]  (hidden comment: RC0603FR-07324KL)
R36  ValueDisplayed: 61.9k  [0603]  (hidden comment: RC0603FR-0761K9L)
R37  ValueDisplayed: 3.09k  [0603]  (hidden comment: RC0603FR-073K09L)
R38  ValueDisplayed: 5.62k  [0603]  (hidden comment: RC0603FR-075K62L)
R39  ValueDisplayed: 12.1k  [0603]  (hidden comment: CRCW060312K1FKEA)
R41  ValueDisplayed: 10.0k  [0603]  (hidden comment: RC0603FR-0710KL)
R42  ValueDisplayed: 300  [0603]  (hidden comment: RC0603FR-07300RL)
R46  ValueDisplayed: 10.0k  [0603]  (hidden comment: RC0603FR-0710KL)
R47  ValueDisplayed: 300  [0603]  (hidden comment: RC0603FR-07300RL)
R48  ValueDisplayed: 10.0k  [0603]  (hidden comment: RC0603FR-0710KL)
R74  ValueDisplayed: 300  [0603]  (hidden comment: RC0603FR-07300RL)
T1  750319933  [FP-750319933_TRANSFORMER_9MM50_9MM78-MFG]
TP6  SW  [Testpoint_Keystone_Miniature]
TP7  5015  [Testpoint_Keystone_Miniature]
TP8  5015  [Testpoint_Keystone_Miniature]
TP9  SS/BIAS  [Testpoint_Keystone_Miniature]
TP10  5015  [Testpoint_Keystone_Miniature]
U3  LM25184QNGURQ1  [NGU0008C]
U6  TPS7B6733QPWPRQ1  [PWP0020D_N]
U7  TPS7B6750QPWPRQ1  [PWP0020D_N]
U8  TPS7B6750QPWPRQ1  [PWP0020D_N]

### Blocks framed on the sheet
*Optional: C32 R19

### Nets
GND: C13.1 C14.1 C28.2 C34.2 C35.2 C36.2 C37.1 C44.2 C45.2 C46.2 D11.2(A) D17.1(K) J5.1 R38.1 R39.1 U3.8(GND) U3.9(PAD) U8.8(GND) U8.13(GND) U8.21(PAD)
GND_Iso: C23.1 C24.1 C25.2 C26.2 C29.1 C30.1 C31.2 C35.1 C40.2 C41.2 C42.2 D8.2(A) D12.1(K) D13.1(K) T1.8 U6.8(GND) U6.13(GND) U6.21(PAD) U7.8(GND) U7.13(GND) U7.21(PAD)  [project net GND_MCU]
PGND: C15.2 C16.2 C17.2 C22.2 D4.2(A) T1.6
VCC5: C41.1 R46.2 R47.2 U7.4(VOUT)  [project net P5V_MCU]
VCC5_LV: C45.1 R48.2 R74.2 U8.4(VOUT)
VCC6: C23.2 C24.2 C25.1 C29.2 C30.2 C40.1 D8.1(K) D10.1(K) R21.2 TP8.1 U6.15(EN) U6.19(VIN) U7.15(EN) U7.19(VIN)
VCC33: C26.1 R41.2 R42.2 U6.4(VOUT)
VDD_Driver: C15.1 C16.1 C17.1 C22.1 D3.1(K) D4.1(K) R18.2 TP10.1
Vbat_prot: C13.2 C14.2 C28.1 C37.2 C44.1 D6.2(A) D9.1(K) D11.1(K) R19.2 R34.2 T1.3 T1.4 TP7.1 U3.3(VIN) U8.15(EN) U8.19(VIN)
NetC12_1: C12.1 R18.1
NetC12_2: C12.2 D3.2(A) T1.5
NetC27_1: C27.1 D9.2(A) J5.2
NetC27_2: C27.2 C34.1
NetC31_1: C31.1 U6.3(DELAY)
NetC32_1: C32.1 R19.1
NetC32_2: C32.2 D18.2(A) R37.2 T1.1 T1.2 TP6.1 U3.1(SW)
NetC33_1: C33.1 R21.1
NetC33_2: C33.2 D10.2(A) T1.7
NetC36_1: C36.1 TP9.1 U3.5(SS/BIAS)
NetC42_1: C42.1 U7.3(DELAY)
NetC46_1: C46.1 U8.3(DELAY)
NetD6_1: D6.1(K) D18.1(K)
NetD12_2: D12.2(A) R42.1
NetD13_2: D13.2(A) R47.1
NetD17_2: D17.2(A) R74.1
NetR34_1: R34.1 R38.2 U3.4(EN/UVLO)
NetR35_1: R35.1 R39.2 U3.7(RSET)
NetR35_2: R35.2 U3.6(TC)
NetR36_1: R36.1 U3.2(FB)
NetR36_2: R36.2 R37.1
NetR41_1: R41.1 U6.1(RESET)
NetR46_1: R46.1 U7.1(RESET)
NetR48_1: R48.1 U8.1(RESET)

Not connected (* = marked no-connect by the designer): U6 2(NC) 5(ADJ/NC)* 6(NC) 7(NC) 9(NC) 10(NC) 11(NC) 12(NC) 14(NC) 16(NC) 17(NC) 18(NC) 20(NC); U7 2(NC) 5(ADJ/NC)* 6(NC) 7(NC) 9(NC) 10(NC) 11(NC) 12(NC) 14(NC) 16(NC) 17(NC) 18(NC) 20(NC); U8 2(NC) 5(ADJ/NC)* 6(NC) 7(NC) 9(NC) 10(NC) 11(NC) 12(NC) 14(NC) 16(NC) 17(NC) 18(NC) 20(NC)

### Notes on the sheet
- (near D9) If = 3A
- (near J5) 12V VBAT
- +16VOUT
- +6VOUT
- (near R38) Turn on 6.3; Turn off 6
- (near U6) input is regulated, 1uF & 10uF should be enough
- Control Card supply 5V

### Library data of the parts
C12 C33 = CMP-0007255-4: CAP, CERM, 22 pF, 100 V, +/- 5%, C0G/NP0, 0603; Manufacturer: MuRata; TaMin_C: -55°C; Polarized: N; SizeAreaWB_mm2: 4.68; Value1: Unknown; U/M: EA; Value: 22pF; TaMax_C: 125°C; SizeZ_mm: 1; SizeX_mm: 1.6; SizeY_mm: 0.8; SizeArea_mm2: 1.28; AEC Category: Q200
C13 C14 C37 = CMP-0009164-2: CAP, CERM, 10 uF, 50 V, +/- 10%, X7S, AEC-Q200 Grade 1, 1210; Manufacturer: TDK; TaMin_C: -55°C; Polarized: N; SizeAreaWB_mm2: 14.7; Value1: 0.002827 ohm; U/M: EA; Value: 10uF; TaMax_C: 125°C; SizeZ_mm: 2.8; SizeX_mm: 3.2; SizeY_mm: 2.5; SizeArea_mm2: 8; CompType: Capacitor; AEC Qualified: Y; Cap_F: 10µF; AEC Grade: 1; AEC Category: Q200; ESR_ohm: 2.827m; IRMS_A: 4.37286A
C15-C17 C29 = CMP-0080552-1: CAP, CERM, 22 µF, 25 V,+/- 10%, X7R, AEC-Q200 Grade 1, 1210; Manufacturer: Taiyo Yuden; TaMin_C: -55°C; Polarized: N; SizeAreaWB_mm2: 14.7; U/M: EA; Value: 22uF; TaMax_C: 125°C; SizeZ_mm: 2.7; SizeX_mm: 3.2; SizeY_mm: 2.5; Cap_Case: 1210; Value2: 25V; SizeArea_mm2: 8; CompType: Capacitor; AEC Qualified: Y; AEC Category: Q200; AEC Grade: 1
C22 C30 = CMP-0079602-1: CAP, CERM, 0.1 µF, 50 V,+/- 10%, X7R, AEC-Q200 Grade 1, 0603; Manufacturer: Kemet; TaMin_C: -55°C; Polarized: N; SizeAreaWB_mm2: 4.68; U/M: EA; TaMax_C: 125°C; SizeZ_mm: 1; SizeX_mm: 1.6; SizeY_mm: 0.8; Value2: 50V; SizeArea_mm2: 1.28; AEC Qualified: Y; Cap_F: 100nF; AEC Category: Q200; ValueDisplayed: 0.1µF
C23 C24 = CMP-0080552-1: CAP, CERM, 22 µF, 25 V,+/- 10%, X7R, AEC-Q200 Grade 1, 1210; Manufacturer: Taiyo Yuden; TaMin_C: -55°C; Polarized: N; SizeAreaWB_mm2: 14.7; U/M: EA; Value: 22uF; TaMax_C: 125°C; SizeZ_mm: 2.7; SizeX_mm: 3.2; SizeY_mm: 2.5; Cap_Case: 1210; Value2: 25V; SizeArea_mm2: 8; AEC Qualified: Y; AEC Category: Q200; AEC Grade: 1
C25 C40 = CMP-0082113-1: CAP, CERM, 1 µF, 25 V,+/- 20%, X7R, AEC-Q200 Grade 1, 0603; Manufacturer: TDK; SizeAreaWB_mm2: 4.68; SizeArea_mm2: 1.28; AEC Qualified: Y; AEC Category: Q200; Value: 1uF; TaMax_C: 125°C; SizeZ_mm: 1; Polarized: N; TaMin_C: -55°C; SizeY_mm: 0.8; U/M: EA; SizeX_mm: 1.6
C26 C41 C45 = CMP-0008003-2: CAP, CERM, 10 uF, 16 V, +/- 20%, X7R, 0805; Manufacturer: Taiyo Yuden; TaMin_C: -55°C; Polarized: N; SizeAreaWB_mm2: 6.75; Value1: Unknown; U/M: EA; Value: 10uF; TaMax_C: 125°C; SizeZ_mm: 1.45; SizeX_mm: 2; SizeY_mm: 1.25; Cap_Case: 0805; SizeArea_mm2: 2.5; AEC Category: Q200
C27 C34 = CMP-0007079-4: CAP, CERM, 0.047 uF, 50 V, +/- 10%, X7R, AEC-Q200 Grade 1, 0603; Manufacturer: TDK; TaMin_C: -55°C; ESR_ohm: 49.007m; Polarized: N; SizeAreaWB_mm2: 4.68; Value1: 0.049007 ohm; U/M: EA; TaMax_C: 125°C; SizeZ_mm: 1; SizeX_mm: 1.6; SizeY_mm: 0.8; SizeArea_mm2: 1.28; AEC Qualified: Y; IRMS_A: 767.528mA; AEC Category: Q200
C28 C31 C42 C46 = CMP-0006861-4: as C2 on sheet TIDM-02012_CoverSheet
C32 = CMP-0007255-4: CAP, CERM, 22 pF, 100 V, +/- 5%, C0G/NP0, 0603; Manufacturer: MuRata; TaMin_C: -55°C; Polarized: N; SizeAreaWB_mm2: 4.68; Value1: Unknown; U/M: EA; Value: 22pF; TaMax_C: 125°C; SizeZ_mm: 1; SizeX_mm: 1.6; SizeY_mm: 0.8; Cap_Case: 0603; Value2: 100V; SizeArea_mm2: 1.28; CompType: Capacitor; AEC Category: Q200
C35 = CMP-0008572-2: CAP, CERM, 1000 pF, 2000 V, +/- 10%, X7R, 1206_190; Manufacturer: Johanson Technology; TaMin_C: -55°C; Polarized: N; SizeAreaWB_mm2: 10.92; Value1: Unknown; U/M: EA; Value: 1000pF; TaMax_C: 125°C; SizeZ_mm: 1.9; SizeX_mm: 3.2; SizeY_mm: 1.6; Cap_Case: 1206; Value2: 2000V; SizeArea_mm2: 5.12; CompType: Capacitor; Cap_F: 1nF; VDC_V: 2kV; AEC Category: Q200
C36 = CMP-0007141-3: CAP, CERM, 0.047 uF, 25 V, +/- 10%, X7R, AEC-Q200 Grade 1, 0603; Manufacturer: MuRata; TaMin_C: -55°C; Polarized: N; SizeAreaWB_mm2: 4.68; Value1: Unknown; U/M: EA; TaMax_C: 125°C; SizeZ_mm: 1; SizeX_mm: 1.6; SizeY_mm: 0.8; Value2: 25V; SizeArea_mm2: 1.28; AEC Qualified: Y; AEC Category: Q200
C44 = CMP-0008821-2: CAP, CERM, 10 uF, 35 V, +/- 10%, X7R, 1206; Manufacturer: Taiyo Yuden; TaMin_C: -55°C; Polarized: N; SizeAreaWB_mm2: 10.92; Value1: Unknown; U/M: EA; Value: 10uF; TaMax_C: 125°C; SizeZ_mm: 1.35; SizeX_mm: 3.2; SizeY_mm: 1.6; SizeArea_mm2: 5.12; Cap_F: 10µF; AEC Category: Q200
D3 D10 = CMP-0028825-2: Diode, Schottky, 60 V, 3 A, AEC-Q101, SOD-123HE; Manufacturer: Fairchild Semiconductor; Value1: 3A; TJmax_C: 150°C; Green_REACh: Incomplete; SizeY_mm: 1.8; SizeZ_mm: 1; Vf_V: 650mV; SizeArea_mm2: 6.66; Green_Lifecycle: Not Set; SizeX_mm: 3.7; Value2: 0.65V; SizeAreaWB_mm2: 13.16; AEC Category: Q101; AEC Qualified: Y
D4 = CMP-0005882-5: Diode, Zener, 18 V, 300 mW, SOD-523; Manufacturer: Diodes Inc.; SizeAreaWB_mm2: 5.13; Power_W: 300mW; AEC Category: Q101; SizeArea_mm2: 1.53; SizeY_mm: 0.9; RJA_CperW: 417; SizeZ_mm: 0.65; Value1: 0.3W; SizeX_mm: 1.7
D6 = CMP-0005514-4: Diode, Zener, 27 V, 3 W, SMA; Manufacturer: Micro Commercial Components; SizeX_mm: 5.59; SizeY_mm: 2.92; RJA_CperW: 226; SizeZ_mm: 2.87; Value1: 3W; SizeArea_mm2: 16.3228; SizeAreaWB_mm2: 37.3428; AEC Category: Q101
D8 = CMP-0005904-4: Diode, Zener, 8.2 V, 300 mW, SOD-523; Manufacturer: Diodes Inc.; RJA_CperW: 417; SizeZ_mm: 0.65; AEC Category: Q101; SizeY_mm: 0.9; SizeAreaWB_mm2: 5.13; Power_W: 300mW; SizeX_mm: 1.7; Value1: 0.3W; SizeArea_mm2: 1.53
D9 = CMP-0077075-2: Diode, Schottky, 100 V, 3 A, AEC-Q101, SMC; Manufacturer: Vishay-Siliconix; Value1: 3A; SizeY_mm: 5.905; Value2: 0.8V; TJmax_C: 175°C; SizeX_mm: 7.94; SizeZ_mm: 2.62; AEC Qualified: Y; Vf_V: 800mV; AEC Category: Q101; Green_REACh: Incomplete; Green_Lifecycle: Not Set; SizeArea_mm2: 46.8857; Vr_V: 100V; SizeAreaWB_mm2: 78.5757; Value: 100V
D11 = CMP-0005729-4: Diode, TVS, Uni, 26 V, 42.1 Vc, AEC-Q101, SMC; Manufacturer: Littelfuse; Vc: 42.1V; Value1: 3000W; Ipp: 71.3A; SizeAreaWB_mm2: 78.5757; AEC Category: Q101; AEC Qualified: Y; SizeArea_mm2: 46.8857; SizeZ_mm: 2.62; Vbr_Max: 31.9V; RJA_CperW: 75; Vbr_Min: 28.9V; Ppk: 3kW; SizeY_mm: 5.905; SizeX_mm: 7.94
D12 D13 D17 = CMP-0002892-3: LED, Yellow, SMD; Manufacturer: Wurth Elektronik; Value1: W; Vf_V: 2V; Type: AlInGaP; Io_A: 20mA
D18 = CMP-0085903-1: Diode, Schottky, 60 V, 3 A, AEC-Q101, SOD-123W; Manufacturer: Nexperia; Io_A: 3A; SizeAreaWB_mm2: 12.15; TJmax_C: 175°C; SizeZ_mm: 1; SizeX_mm: 3.5; SizeY_mm: 1.7; Vf_V: 620mV; Value2: 0.62V; SizeArea_mm2: 5.95; AEC Qualified: Y; AEC Category: Q101
J5 = CMP-0084907-1: as J2 on sheet TIDM-02012_CoverSheet
R18 R21 = CMP-0084243-1: RES, 100, 1%, 0.25 W, AEC-Q200 Grade 0, 0603; Manufacturer: Vishay-Dale; Power_W: 250mW; TempCo: 100 ppm/C; SizeAreaWB_mm2: 4.68; Value_Code: 100R; Value: 100; EIA_Code: E96; SizeX_mm: 1.6; SizeY_mm: 0.8; SizeZ_mm: 1; Value2: 0.25W; SizeArea_mm2: 1.28; AEC Qualified: Y; AEC Grade: 0; AEC Category: Q200
R19 = CMP-0021991-4: RES, 100, 1%, 0.1 W, AEC-Q200 Grade 0, 0603; Manufacturer: Vishay-Dale; Power_W: 100mW; TempCo: 100 ppm/C; Value_Code: 100R; Value: 100; EIA_Code: E96; SizeX_mm: 1.6; SizeY_mm: 0.8; SizeZ_mm: 1; Value2: 0.1W; SizeArea_mm2: 1.28; AEC Qualified: Y; VDC_V: 75V; AEC Category: Q200; AEC Grade: 0
R34 = CMP-0022841-5: RES, 17.8 k, 1%, 0.1 W, 0603; Manufacturer: Yageo; Power_W: 100mW; TempCo: 100 ppm/C; Value_Code: 17k8; Value: 17.8k; EIA_Code: E96; SizeX_mm: 1.6; SizeY_mm: 0.8; SizeZ_mm: 1; Value2: 0.1W; SizeArea_mm2: 1.28; CompType: Resistor; AEC Qualified: N; VDC_V: 75V; AEC Category: Q200; SizeAreaWB_mm2: 4.68
R35 = CMP-0023028-4: RES, 324 k, 1%, 0.1 W, 0603; Manufacturer: Yageo; Power_W: 100mW; TempCo: 100 ppm/C; Value: 324k; EIA_Code: E96; SizeX_mm: 1.6; SizeY_mm: 0.8; SizeZ_mm: 1; Value2: 0.1W; SizeArea_mm2: 1.28; AEC Qualified: N; VDC_V: 75V; AEC Category: Q200; SizeAreaWB_mm2: 4.68
R36 = CMP-0023216-5: RES, 61.9 k, 1%, 0.1 W, 0603; Manufacturer: Yageo; Power_W: 100mW; TempCo: 100 ppm/C; Value_Code: 61k9; Value: 61.9k; EIA_Code: E96; SizeX_mm: 1.6; SizeY_mm: 0.8; SizeZ_mm: 1; Value2: 0.1W; SizeArea_mm2: 1.28; AEC Qualified: N; VDC_V: 75V; AEC Category: Q200; SizeAreaWB_mm2: 4.68
R37 = CMP-0023077-5: RES, 3.09 k, 1%, 0.1 W, 0603; Manufacturer: Yageo; Power_W: 100mW; TempCo: 100 ppm/C; Value_Code: 3k09; Value: 3.09k; EIA_Code: E96; SizeX_mm: 1.6; SizeY_mm: 0.8; SizeZ_mm: 1; Value2: 0.1W; SizeArea_mm2: 1.28; AEC Qualified: N; VDC_V: 75V; AEC Category: Q200; SizeAreaWB_mm2: 4.68
R38 = CMP-0023202-5: RES, 5.62 k, 1%, 0.1 W, 0603; Manufacturer: Yageo; Power_W: 100mW; TempCo: 100 ppm/C; Value_Code: 5k62; Value: 5.62k; EIA_Code: E96; SizeX_mm: 1.6; SizeY_mm: 0.8; SizeZ_mm: 1; Value2: 0.1W; SizeArea_mm2: 1.28; AEC Qualified: N; VDC_V: 75V; AEC Category: Q200; SizeAreaWB_mm2: 4.68
R39 = CMP-0022030-4: RES, 12.1 k, 1%, 0.1 W, AEC-Q200 Grade 0, 0603; Manufacturer: Vishay-Dale; Power_W: 100mW; TempCo: 100 ppm/C; Value_Code: 12k1; Value: 12.1k; EIA_Code: E96; SizeX_mm: 1.6; SizeY_mm: 0.8; SizeZ_mm: 1; Value2: 0.1W; SizeArea_mm2: 1.28; AEC Qualified: Y; VDC_V: 75V; AEC Category: Q200; AEC Grade: 0
R41 R46 R48 = CMP-0022746-5: as R3 on sheet TIDM-02012_CoverSheet
R42 R47 R74 = CMP-0023013-5: RES, 300, 1%, 0.1 W, 0603; Manufacturer: Yageo; Power_W: 100mW; TempCo: 100 ppm/C; Value_Code: 300R; Value: 300; SizeX_mm: 1.6; SizeY_mm: 0.8; SizeZ_mm: 1; Value2: 0.1W; SizeArea_mm2: 1.28; AEC Qualified: N; VDC_V: 75V; AEC Category: Q200; SizeAreaWB_mm2: 4.68
T1 = CMP-0094165-1: Bobbin Packages EP7 8-Terminal, SMT, Horizonta; Manufacturer: Wurth Electronics; Frequency_Fixed: 350kHz; Ind_H: 8.1µH; SizeZ_mm: 10.54mm; Ns1toNp: 1:1:2.64; AEC Qualified: No; DCR_ohm: 42m
TP6 TP9 = CMP-0055152-1: Test Point, Miniature, SMT; Manufacturer: Keystone; PartNumber: 5015; CNHeader: FALSE; Green_Lifecycle: Active; Green_REACh: Passed; CT: TRUE
TP7 TP8 TP10 = CMP-0055152-1: as TP1 on sheet TIDM-02012_CoverSheet
U3 = CMP-0860959-2: 42-VIN PSR Flyback DC/DC Converter with 65-V, 4-A Integrated MOSFET, NGU0008C (WSON-8); Manufacturer: Texas Instruments; SizeArea_mm2: 16; SizeY_mm: 4; SizeAreaWB_mm2: 25; CompType: IC; AEC Category: Q200; SizeZ_mm: 0.8; AEC Qualified: Y
U6 = CMP-0085806-1: Automotive 450mA High-Voltage Ultra-Low-Iq Low-Dropout Regulator, PWP0020D (HTSSOP-20); Manufacturer: Texas Instruments; SizeArea_mm2: 41.6; AEC Category: Q200; SizeZ_mm: 1.2; CompType: IC; AEC Qualified: Y; SizeAreaWB_mm2: 71.4; SizeY_mm: 6.5; SizeX_mm: 6.4
U7 U8 = CMP-0085807-1: Automotive 450mA High-Voltage Ultra-Low-Iq Low-Dropout Regulator, PWP0020D (HTSSOP-20); Alternate Manufacturer: Texas Instruments; SizeAreaWB_mm2: 71.4; SizeY_mm: 6.5; AEC Qualified: Y; SizeX_mm: 6.4; AEC Category: Q200; Green_Lifecycle: Active; CompType: IC; SizeZ_mm: 1.2; SizeArea_mm2: 41.6; Green_REACh: Passed

## Sheet TIDM-02012_Half_Bridge.SchDoc
size 431 x 279 mm; Date: Not shown in title block; ApprovedBy: Not shown in title block; CheckedBy: Not shown in title block; Author: Not shown in title block; CompanyName: Not shown in title block; Engineer: Not shown in title block; Organization: Not shown in title block; Address1: Not shown in title block; Address2: Not shown in title block; Address3: Not shown in title block; Address4: Not shown in title block; DocumentNumber: 2; Revision: Use project parameter SCH_Rev; SheetNumber: 3; SheetTotal: 5; PageSetup: Record=PageOptions¦CenterHorizontal=True¦CenterVertical=True¦PrintScale=1.00¦XCorrection=1.00¦YCorrection=1.00¦PrintKind=0¦BorderSize=5000000¦LeftOffset=0¦BottomOffset=0¦Orientation=2¦PaperLength=1000¦PaperWidth=1000¦Scale=100¦PaperSource=15¦PrintQuality=600¦MediaType=1¦DitherType=10¦PaperKind=Letter¦PrintScaleMode=1
Used 3 times, as channels U, W, V. Parts and nets are listed once, with the designators drawn on the sheet.
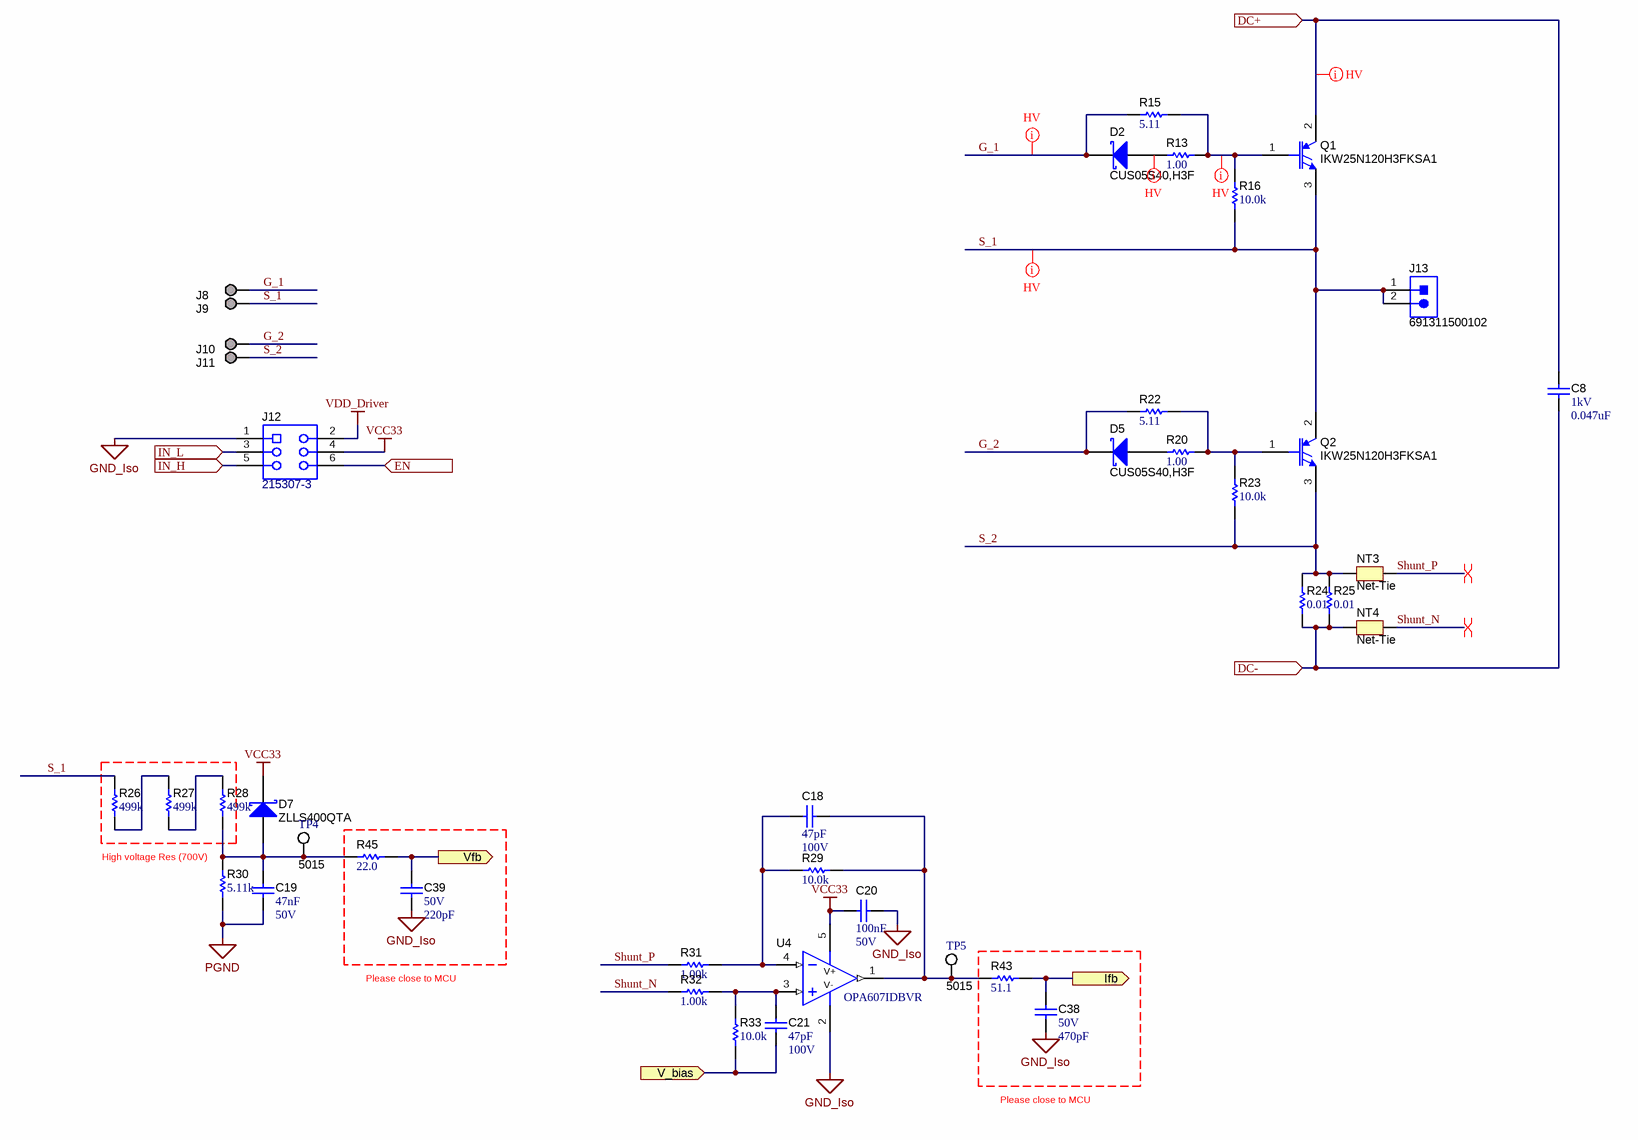
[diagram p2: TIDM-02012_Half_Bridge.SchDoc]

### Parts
C8  VDC_V: 1kV  ValueDisplayed: 0.047uF  [1812]  (hidden comment: C1812V473KDRACTU)
C18  ValueDisplayed: 47pF  VDC_V: 100V  [0603]  (hidden comment: C0603C470J1GACAUTO)
C19  Cap_F: 47nF  VDC_V: 50V  [0603]  (hidden comment: 06035C473JAT2A)
C20  Cap_F: 100nF  VDC_V: 50V  [0603]  (hidden comment: C0603C104K5RACTU)
C21  ValueDisplayed: 47pF  VDC_V: 100V  [0603]  (hidden comment: C0603C470J1GACAUTO)
C38  VDC_V: 50V  ValueDisplayed: 470pF  [0603]  (hidden comment: GRM1885C1H471JA01D)
C39  VDC_V: 50V  ValueDisplayed: 220pF  [0603]  (hidden comment: GRM1885C1H221JA01D)
D2  CUS05S40,H3F  [SOD-323]
D5  CUS05S40,H3F  [SOD-323]
D7  ZLLS400QTA  [SOD-323]
J8  0312-0-15-15-34-27-10-0  [Mill-Max_0312-0-15-15-34-27-10-0]  (value not drawn)
J9  0312-0-15-15-34-27-10-0  [Mill-Max_0312-0-15-15-34-27-10-0]  (value not drawn)
J10  0312-0-15-15-34-27-10-0  [Mill-Max_0312-0-15-15-34-27-10-0]  (value not drawn)
J11  0312-0-15-15-34-27-10-0  [Mill-Max_0312-0-15-15-34-27-10-0]  (value not drawn)
J12  215307-3  [TE_215307-3]
J13  691311500102  [Wurth_691311500102]
NT3  Net-Tie  [Net-Tie_10milWide_30milLong]  (net tie, no BOM)
NT4  Net-Tie  [Net-Tie_10milWide_30milLong]  (net tie, no BOM)
Q1  IKW25N120H3FKSA1  [TO-247_Horizontal_Down]
Q2  IKW25N120H3FKSA1  [TO-247_Horizontal_Down]
R13  ValueDisplayed: 1.00  [0603]  (hidden comment: CRCW06031R00FKEA)
R15  ValueDisplayed: 5.11  [0603]  (hidden comment: RC0603FR-075R11L)
R16  ValueDisplayed: 10.0k  [0603]  (hidden comment: RC0603FR-0710KL)
R20  ValueDisplayed: 1.00  [0603]  (hidden comment: CRCW06031R00FKEA)
R22  ValueDisplayed: 5.11  [0603]  (hidden comment: RC0603FR-075R11L)
R23  ValueDisplayed: 10.0k  [0603]  (hidden comment: RC0603FR-0710KL)
R24  ValueDisplayed: 0.01  [1206]  (hidden comment: WSLP1206R0100FEA)
R25  ValueDisplayed: 0.01  [1206]  (hidden comment: WSLP1206R0100FEA)
R26  ValueDisplayed: 499k  [1206]  (hidden comment: ERJ-8ENF4993V)
R27  ValueDisplayed: 499k  [1206]  (hidden comment: ERJ-8ENF4993V)
R28  ValueDisplayed: 499k  [1206]  (hidden comment: ERJ-8ENF4993V)
R29  ValueDisplayed: 10.0k  [0603]  (hidden comment: RC0603FR-0710KL)
R30  ValueDisplayed: 5.11k  [1206]  (hidden comment: ERJ-8ENF5111V)
R31  ValueDisplayed: 1.00k  [0603]  (hidden comment: RC0603FR-071KL)
R32  ValueDisplayed: 1.00k  [0603]  (hidden comment: RC0603FR-071KL)
R33  ValueDisplayed: 10.0k  [0603]  (hidden comment: RC0603FR-0710KL)
R43  ValueDisplayed: 51.1  [0603]  (hidden comment: RC0603FR-0751R1L)
R45  ValueDisplayed: 22.0  [0603]  (hidden comment: RC0603FR-0722RL)
TP4  5015  [Testpoint_Keystone_Miniature]
TP5  5015  [Testpoint_Keystone_Miniature]
U4  OPA607IDBVR  [DBV0005A_N]

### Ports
DC+ (in), DC- (in), EN (in), Ifb (out), IN_H (in), IN_L (in), V_bias (in), Vfb (out)

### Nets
GND_Iso: C20.1 C38.2 C39.2 J12.1 U4.2(V-)
PGND: C19.2 R30.1
VCC33: C20.2 D7.1(K) J12.4 U4.5(V+)
VDD_Driver: J12.2
DC+: C8.1 Q1.2(C) ; port DC+
DC-: C8.2 NT4.1 R24.1 R25.1 ; port DC-
EN: J12.6 ; port EN
G_1: D2.1(K) J8.1 R15.1
G_2: D5.1(K) J10.1 R22.1
Ifb: C38.1 R43.2 ; port Ifb
IN_H: J12.5 ; port IN_H
IN_L: J12.3 ; port IN_L
S_1: J9.1 J13.1 J13.2 Q1.3(E) Q2.2(C) R16.1 R26.2
S_2: J11.1 NT3.1 Q2.3(E) R23.1 R24.2 R25.2
Shunt_N: NT4.2 R32.1
Shunt_P: NT3.2 R31.1
V_bias: C21.2 R33.1 ; port V_bias
Vfb: C39.1 R45.2 ; port Vfb
NetC18_1: C18.1 R29.2 R43.1 TP5.1 U4.1(OUT)
NetC18_2: C18.2 R29.1 R31.2 U4.4(IN-)
NetC19_1: C19.1 D7.2(A) R28.1 R30.2 R45.1 TP4.1
NetC21_1: C21.1 R32.2 R33.2 U4.3(IN+)
NetD2_2: D2.2(A) R13.1
NetD5_2: D5.2(A) R20.1
NetQ1_1: Q1.1(G) R13.2 R15.2 R16.2
NetQ2_1: Q2.1(G) R20.2 R22.2 R23.2
NetR26_1: R26.1 R27.2
NetR27_1: R27.1 R28.2

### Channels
U: designators end in U; ports DC+=VBUS DC-=DC- EN=EN_DRV Ifb=Ifb_U IN_H=PWM1A IN_L=PWM1B V_bias=V_bias_1v65 Vfb=Vfb_U
W: designators end in W; ports DC+=VBUS DC-=DC- EN=EN_DRV Ifb=Ifb_W IN_H=PWM3A IN_L=PWM3B V_bias=V_bias_1v65 Vfb=Vfb_W
V: designators end in V; ports DC+=VBUS DC-=DC- EN=EN_DRV Ifb=Ifb_V IN_H=PWM2A IN_L=PWM2B V_bias=V_bias_1v65 Vfb=Vfb_V

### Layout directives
differential pair: Shunt_N_U, Shunt_P_U
net class HV: G_1_U, NetD2U_2, NetQ1U_1, S_1_U
net class HVDC: VBUS

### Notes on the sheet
- (near R30) High voltage Res (700V)
- Please close to MCU

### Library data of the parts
C8 = CMP-0009325-2: CAP, CERM, 0.047 uF, 1000 V, +/- 10%, X7R, 1812; Manufacturer: Kemet; TaMin_C: -55°C; Polarized: N; SizeAreaWB_mm2: 23.1; Value1: Unknown; U/M: EA; TaMax_C: 125°C; SizeZ_mm: 1.35; SizeX_mm: 4.5; SizeY_mm: 3.2; Value2: 1000V; SizeArea_mm2: 14.4; Cap_F: 47nF; AEC Category: Q200
C18 C21 = CMP-0085572-1: as C1 on sheet TIDM-02012_CoverSheet
C19 = CMP-0085252-1: as C5 on sheet TIDM-02012_CoverSheet
C20 = CMP-0006861-4: as C2 on sheet TIDM-02012_CoverSheet
C38 = CMP-0007221-4: as C7 on sheet TIDM-02012_CoverSheet
C39 = CMP-0007197-4: as C43 on sheet TIDM-02012_CoverSheet
D2 D5 = CMP-0028748-2: Diode, Schottky, 40 V, 0.5 A, SOD-323; Manufacturer: Toshiba; TJmax_C: 125°C; Value: 40V; SizeZ_mm: 1; Value1: 0.5A; Value2: 0.6V; Io_A: 500mA; AEC Qualified: N; SizeAreaWB_mm2: 8.695; SizeY_mm: 1.35; SizeArea_mm2: 3.645; SizeX_mm: 2.7; AEC Category: Q101; Vf_V: 600mV; Green_Lifecycle: Not Set; Green_REACh: Incomplete
D7 = CMP-0028792-2: as D1 on sheet TIDM-02012_CoverSheet
J8-J11 = CMP-0055026-1: Manufacturer: Mill-Max; CNHeader: FALSE; Green_Lifecycle: Active; Gender: Female; Green_REACh: Passed; CompType: Pin Receptacle; ContactFinish: Gold
J12 = CMP-0082603-1: Receptacle, 2.54mm, 3x2, Tin, TH; Manufacturer: TE Connectivity; Pitch_mm: 2.54; Gender: Female; Cert_UL: Y; Row_Count: 2; CompType: Socket Strip
J13 = CMP-0084907-1: as J2 on sheet TIDM-02012_CoverSheet
NT3 NT4 = CMP-0078142-4: Single point connection between nets.
Q1 Q2 = CMP-0000526-4: Transistor, IGBT, 1200 V, 50 A, TO-247; Manufacturer: Infineon Technologies; TaMax_C: 175°C; AEC Category: Q101; IcRated_A: 50A; SizeArea_mm2: 78; SizeY_mm: 5; Vceo_V: 1.2kV; Value1: 50 A; Value: 1200 V; Vcesat1_V: 2.05V; AEC Qualified: N; SizeX_mm: 15.6; NPN: 0; SizeZ_mm: 25; TaMin_C: -40°C; SizeAreaWB_mm2: 123.2
R13 R20 = CMP-0022170-4: RES, 1.00, 1%, 0.1 W, AEC-Q200 Grade 0, 0603; Manufacturer: Vishay-Dale; Power_W: 100mW; TempCo: 100 ppm/C; Value_Code: 1R00; Value: 1.00; EIA_Code: E96; Res_ohm: 1; SizeX_mm: 1.6; SizeY_mm: 0.8; Value2: 0.1W; SizeArea_mm2: 1.28; AEC Qualified: Y; VDC_V: 75V; AEC Category: Q200; AEC Grade: 0
R15 R22 = CMP-0023206-5: RES, 5.11, 1%, 0.1 W, 0603; Manufacturer: Yageo; Power_W: 100mW; TempCo: 200 ppm/C; Value_Code: 5R11; Value: 5.11; EIA_Code: E96; SizeX_mm: 1.6; SizeY_mm: 0.8; SizeZ_mm: 1; Value2: 0.1W; SizeArea_mm2: 1.28; AEC Qualified: N; VDC_V: 75V; AEC Category: Q200; SizeAreaWB_mm2: 4.68
R16 R23 R29 R33 = CMP-0022746-5: as R3 on sheet TIDM-02012_CoverSheet
R24 R25 = CMP-0018570-2: as R1 on sheet TIDM-02012_CoverSheet
R26-R28 = CMP-0017631-3: as R6 on sheet TIDM-02012_CoverSheet
R30 = CMP-0017634-3: as R11 on sheet TIDM-02012_CoverSheet
R31 R32 = CMP-0022895-5: as R4 on sheet TIDM-02012_CoverSheet
R43 = CMP-0023168-5: as R40 on sheet TIDM-02012_CoverSheet
R45 = CMP-0022928-4: as R75 on sheet TIDM-02012_CoverSheet
TP4 TP5 = CMP-0055152-1: as TP1 on sheet TIDM-02012_CoverSheet
U4 = CMP-0861047-2: as U1 on sheet TIDM-02012_CoverSheet

## Sheet TIDM-02012_Hardware.SchDoc
size 431 x 279 mm; Date: Not shown in title block; ApprovedBy: Not shown in title block; CheckedBy: Not shown in title block; Author: Not shown in title block; CompanyName: Not shown in title block; Engineer: Not shown in title block; Organization: Not shown in title block; Address1: Not shown in title block; Address2: Not shown in title block; Address3: Not shown in title block; Address4: Not shown in title block; DocumentNumber: 3; Revision: Use project parameter SCH_Rev; SheetNumber: 2; SheetTotal: 5; PageSetup: Record=PageOptions¦CenterHorizontal=True¦CenterVertical=True¦PrintScale=1.00¦XCorrection=1.00¦YCorrection=1.00¦PrintKind=0¦BorderSize=5000000¦LeftOffset=0¦BottomOffset=0¦Orientation=2¦PaperLength=1000¦PaperWidth=1000¦Scale=100¦PaperSource=15¦PrintQuality=600¦MediaType=1¦DitherType=10¦PaperKind=Letter¦PrintScaleMode=1
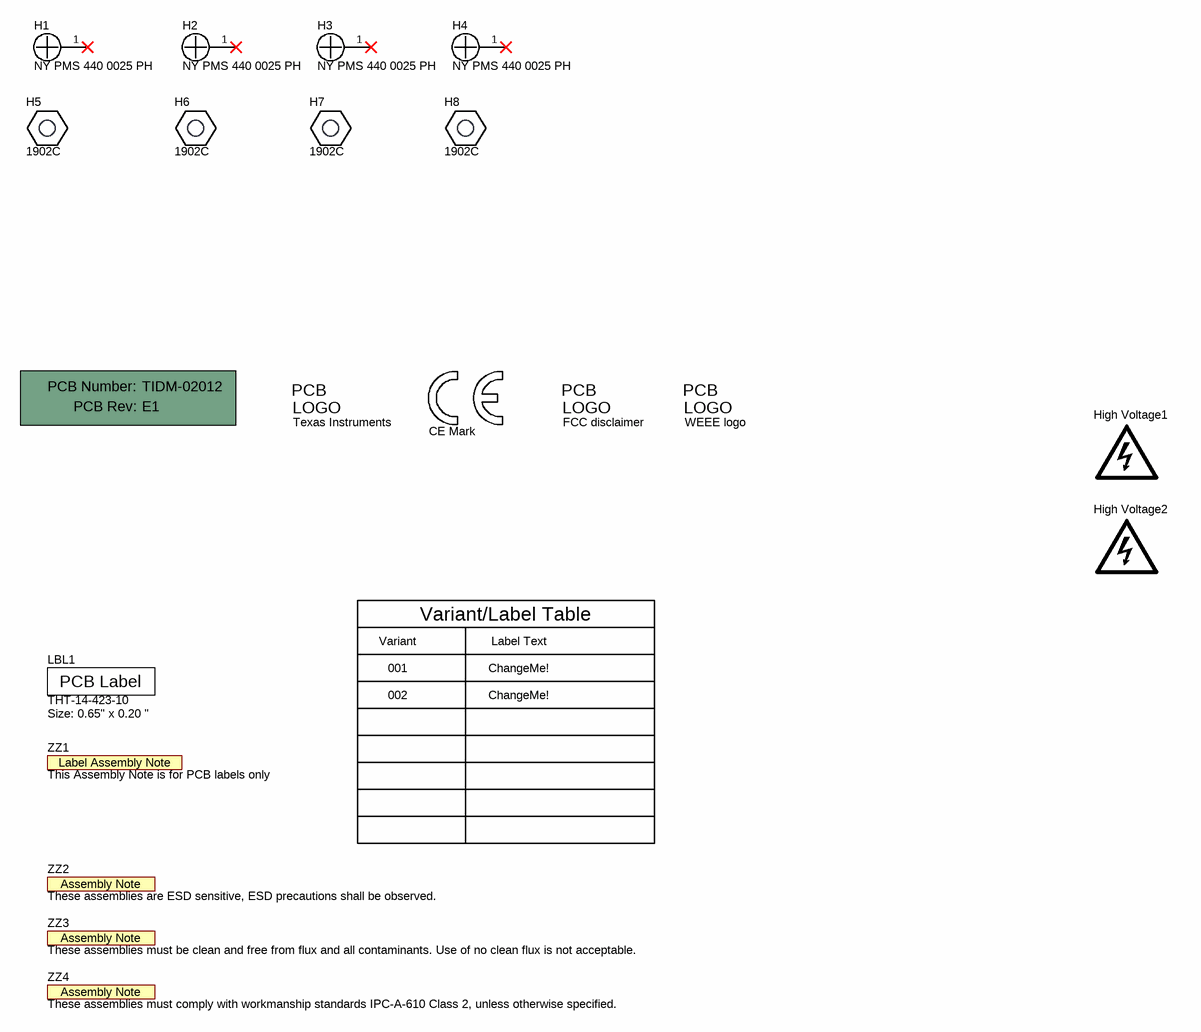
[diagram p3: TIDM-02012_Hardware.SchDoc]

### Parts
!PCB  Printed Circuit Board  (value not drawn)  (mechanical)
H1  NY PMS 440 0025 PH  [NY PMS 440 0025 PH]
H2  NY PMS 440 0025 PH  [NY PMS 440 0025 PH]
H3  NY PMS 440 0025 PH  [NY PMS 440 0025 PH]
H4  NY PMS 440 0025 PH  [NY PMS 440 0025 PH]
H5  1902C  [Keystone_1902C]
H6  1902C  [Keystone_1902C]
H7  1902C  [Keystone_1902C]
H8  1902C  [Keystone_1902C]
High_Voltage1  DANGER HIGH VOLTAGE  [IEC_HighVoltage_Medium]  (value not drawn)  (no BOM)
High_Voltage2  DANGER HIGH VOLTAGE  [IEC_HighVoltage_Medium]  (value not drawn)  (no BOM)
LBL1  THT-14-423-10  Note: Size: 0.65" x 0.20 "  [Label_650x200]
Logo1  Texas Instruments  [TI_Stacked_Overlay_Small]  (no BOM)
Logo2  CE Mark  [CE_Mark_5mm]  (no BOM)
Logo3  FCC disclaimer  [FCC_disclaimer]  (no BOM)
Logo4  WEEE logo  [WEEE_Minimum]  (no BOM)
ZZ1  This Assembly Note is for PCB labels only  [AssemblyNoteLabel]  (no BOM)
ZZ2  These assemblies are ESD sensitive, ESD precautions shall be observed.  [AssemblyNote]  (no BOM)
ZZ3  These assemblies must be clean and free from flux and all contaminants. Use of no clean flux is not acceptable.  [AssemblyNote]  (no BOM)
ZZ4  These assemblies must comply with workmanship standards IPC-A-610 Class 2, unless otherwise specified.  [AssemblyNote]  (no BOM)

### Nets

Not connected (* = marked no-connect by the designer): H1 1*; H2 1*; H3 1*; H4 1*

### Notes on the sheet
- Variant
- Variant/Label Table
- Label Text
- 001
- 002
- ChangeMe!

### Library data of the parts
!PCB = CMP-0003618-2: Manufacturer: Any; PartNumber: TIDM-02012
H1-H4 = CMP-0003617-1: Machine Screw, Round, #4-40 x 1/4, Nylon, Philips panhead; Manufacturer: B&F Fastener Supply; CompType: Hardware
H5-H8 = CMP-0003610-1: Standoff, Hex, 0.5"L #4-40 Nylon; Manufacturer: Keystone; CompType: Hardware
High_Voltage1 High_Voltage2 = CMP-0074835-1: IEC 61010-1 High Voltage Warning; SymbolCreator: a0412235
LBL1 = CMP-0003625-1: Thermal Transfer Printable Labels, 0.650" W x 0.200" H - 10,000 per roll; Manufacturer: Brady; CompType: Label
Logo1 = CMP-0074838-1: Texas Instrument Corporate Signature; SymbolCreator: a0412235; Lib Reference: TI_Logo; Library Reference: Logo
Logo2 = CMP-0074844-1: SymbolCreator: a0412235
Logo3 = CMP-0074847-1: FCC_disclaimer; Library Reference: Logo
Logo4 = CMP-0074769-1
ZZ1 = CMP-0003616-3
ZZ2 = CMP-0077236-1
ZZ3 = CMP-0077237-1
ZZ4 = CMP-0077238-1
